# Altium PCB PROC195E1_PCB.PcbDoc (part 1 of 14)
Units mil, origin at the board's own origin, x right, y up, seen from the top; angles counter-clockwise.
Board outline 3110.24 x 2500 mil, 10 copper layers (Top Layer, L02_GND1, L03_SIG1, L04_GND2, L05_PWR1, L06_PWR2, L07_GND3, L08_SIG2, L09_GND4, Bottom Layer), stack 66.407 mil thick; 571 components, 538 nets, 6726 pads, 1286 vias.
Unrouted connection lines stored in the file: 4.
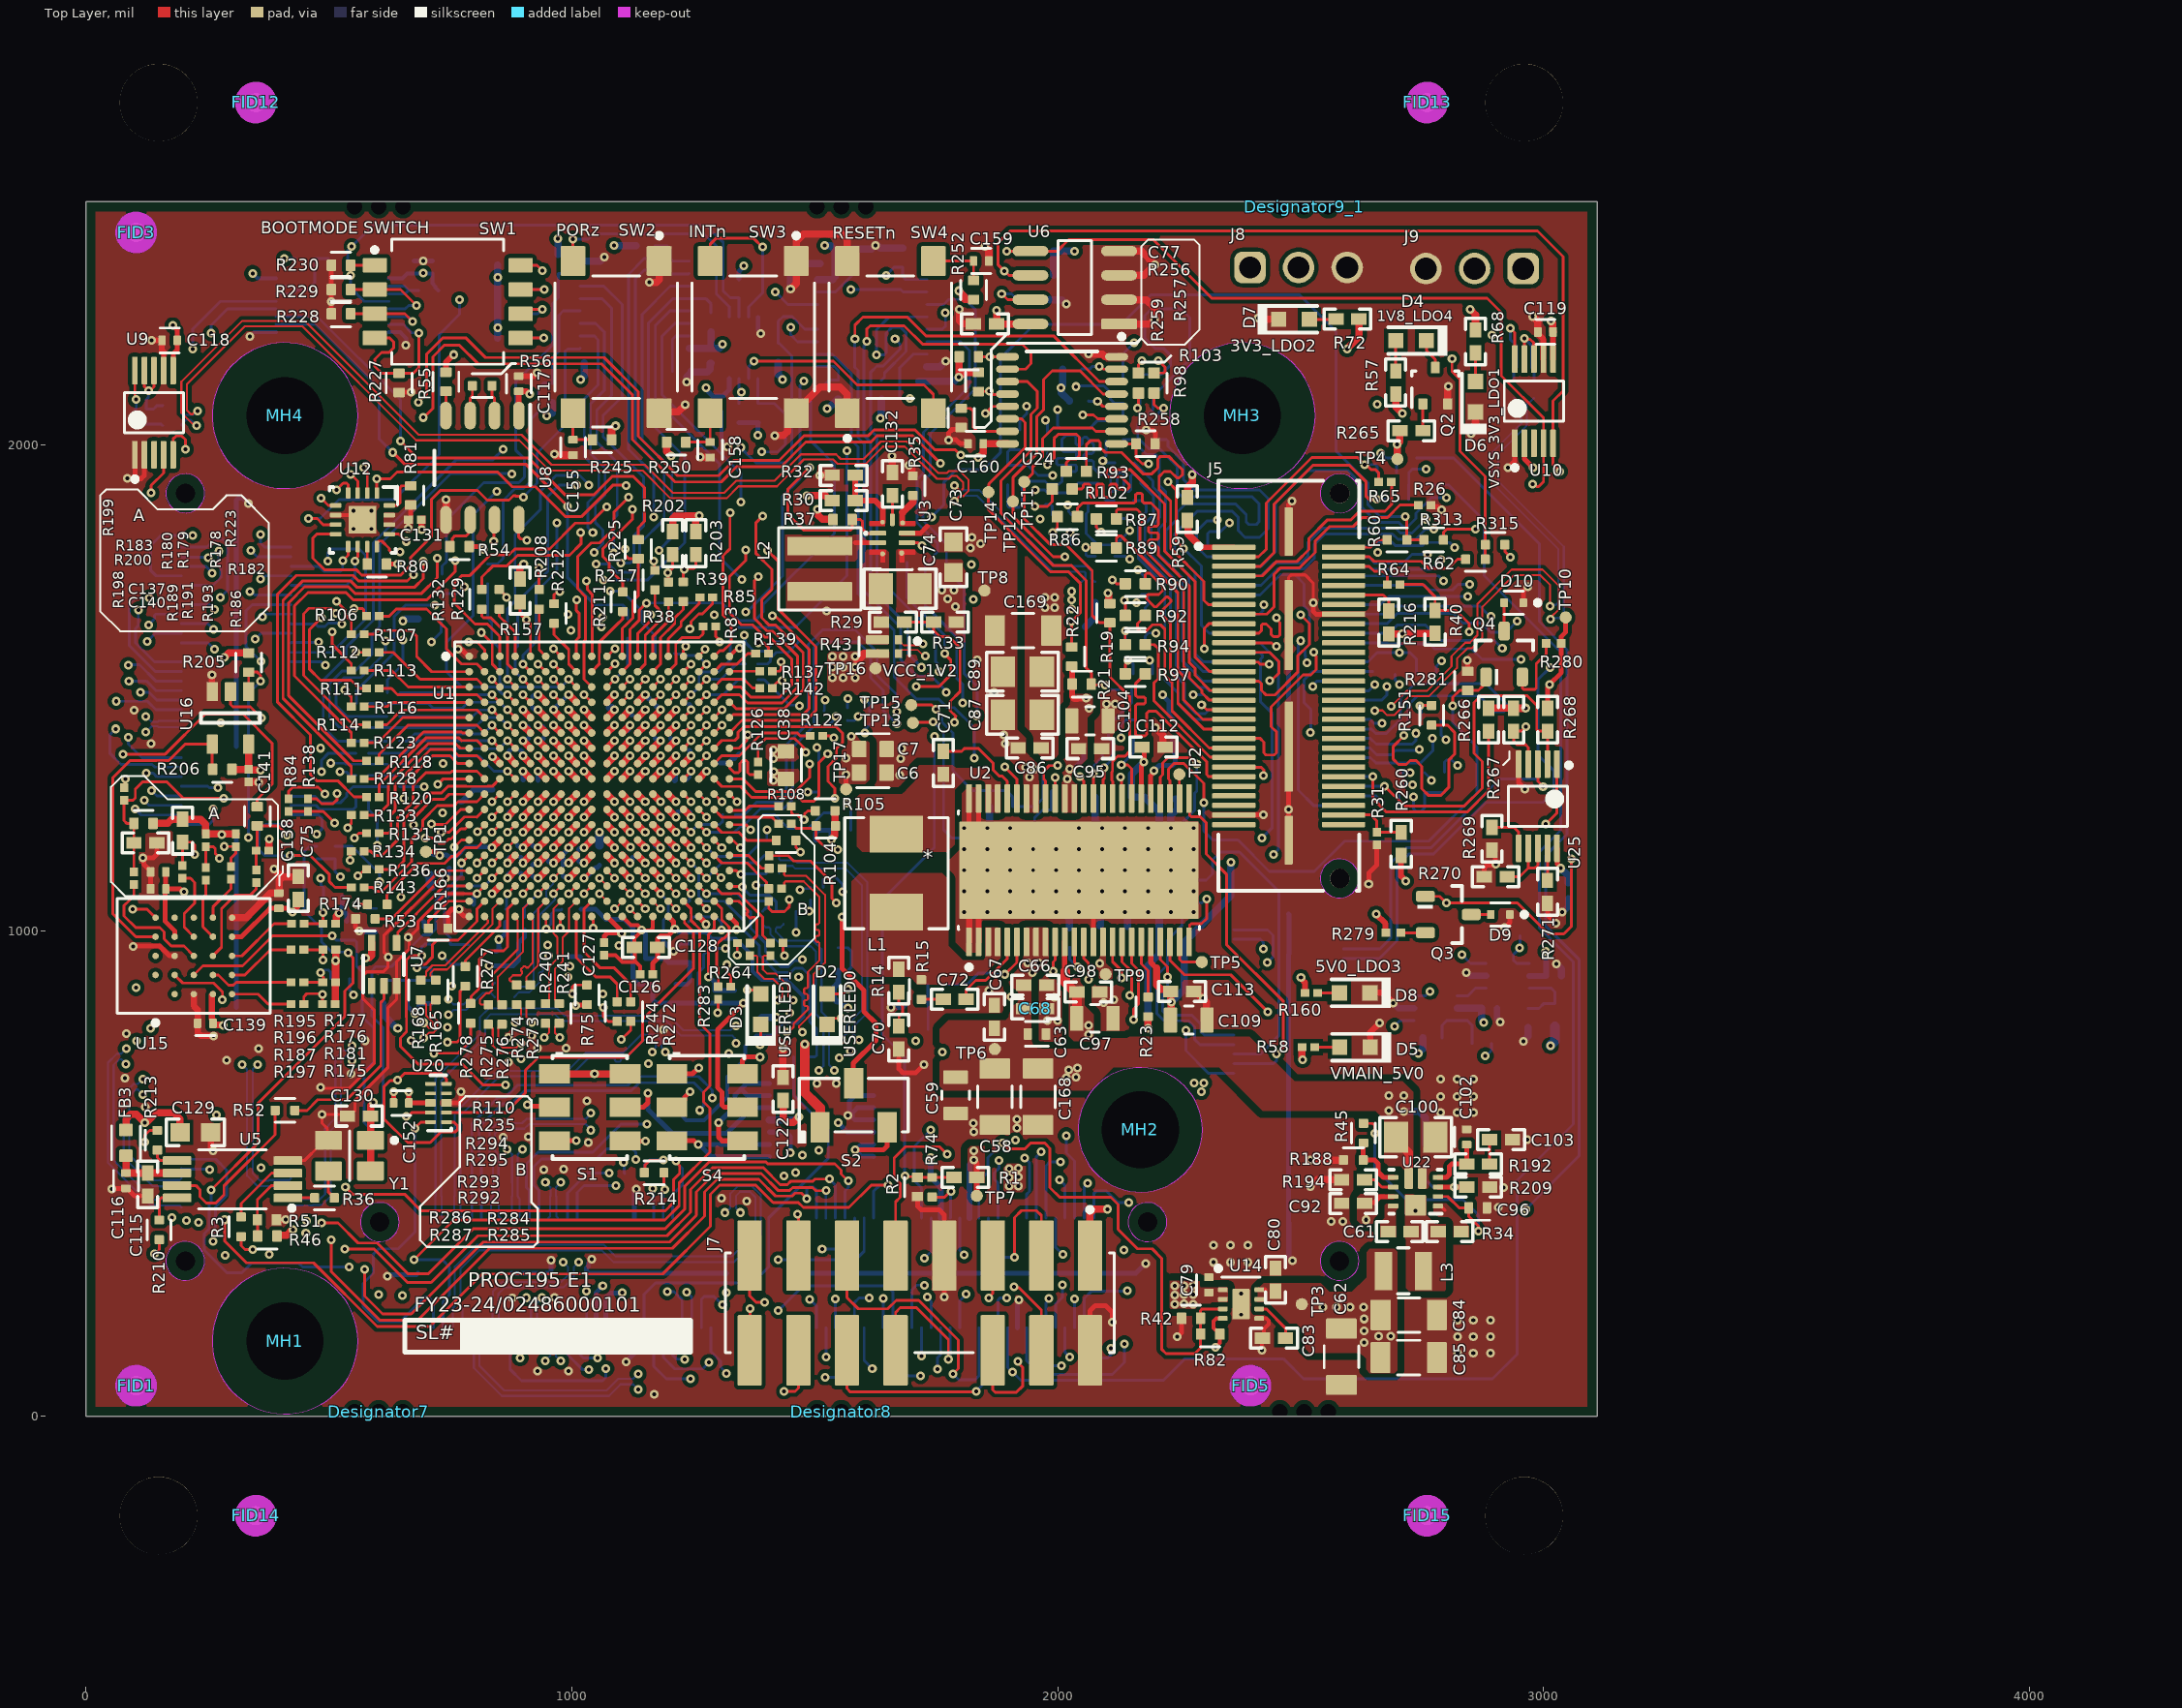
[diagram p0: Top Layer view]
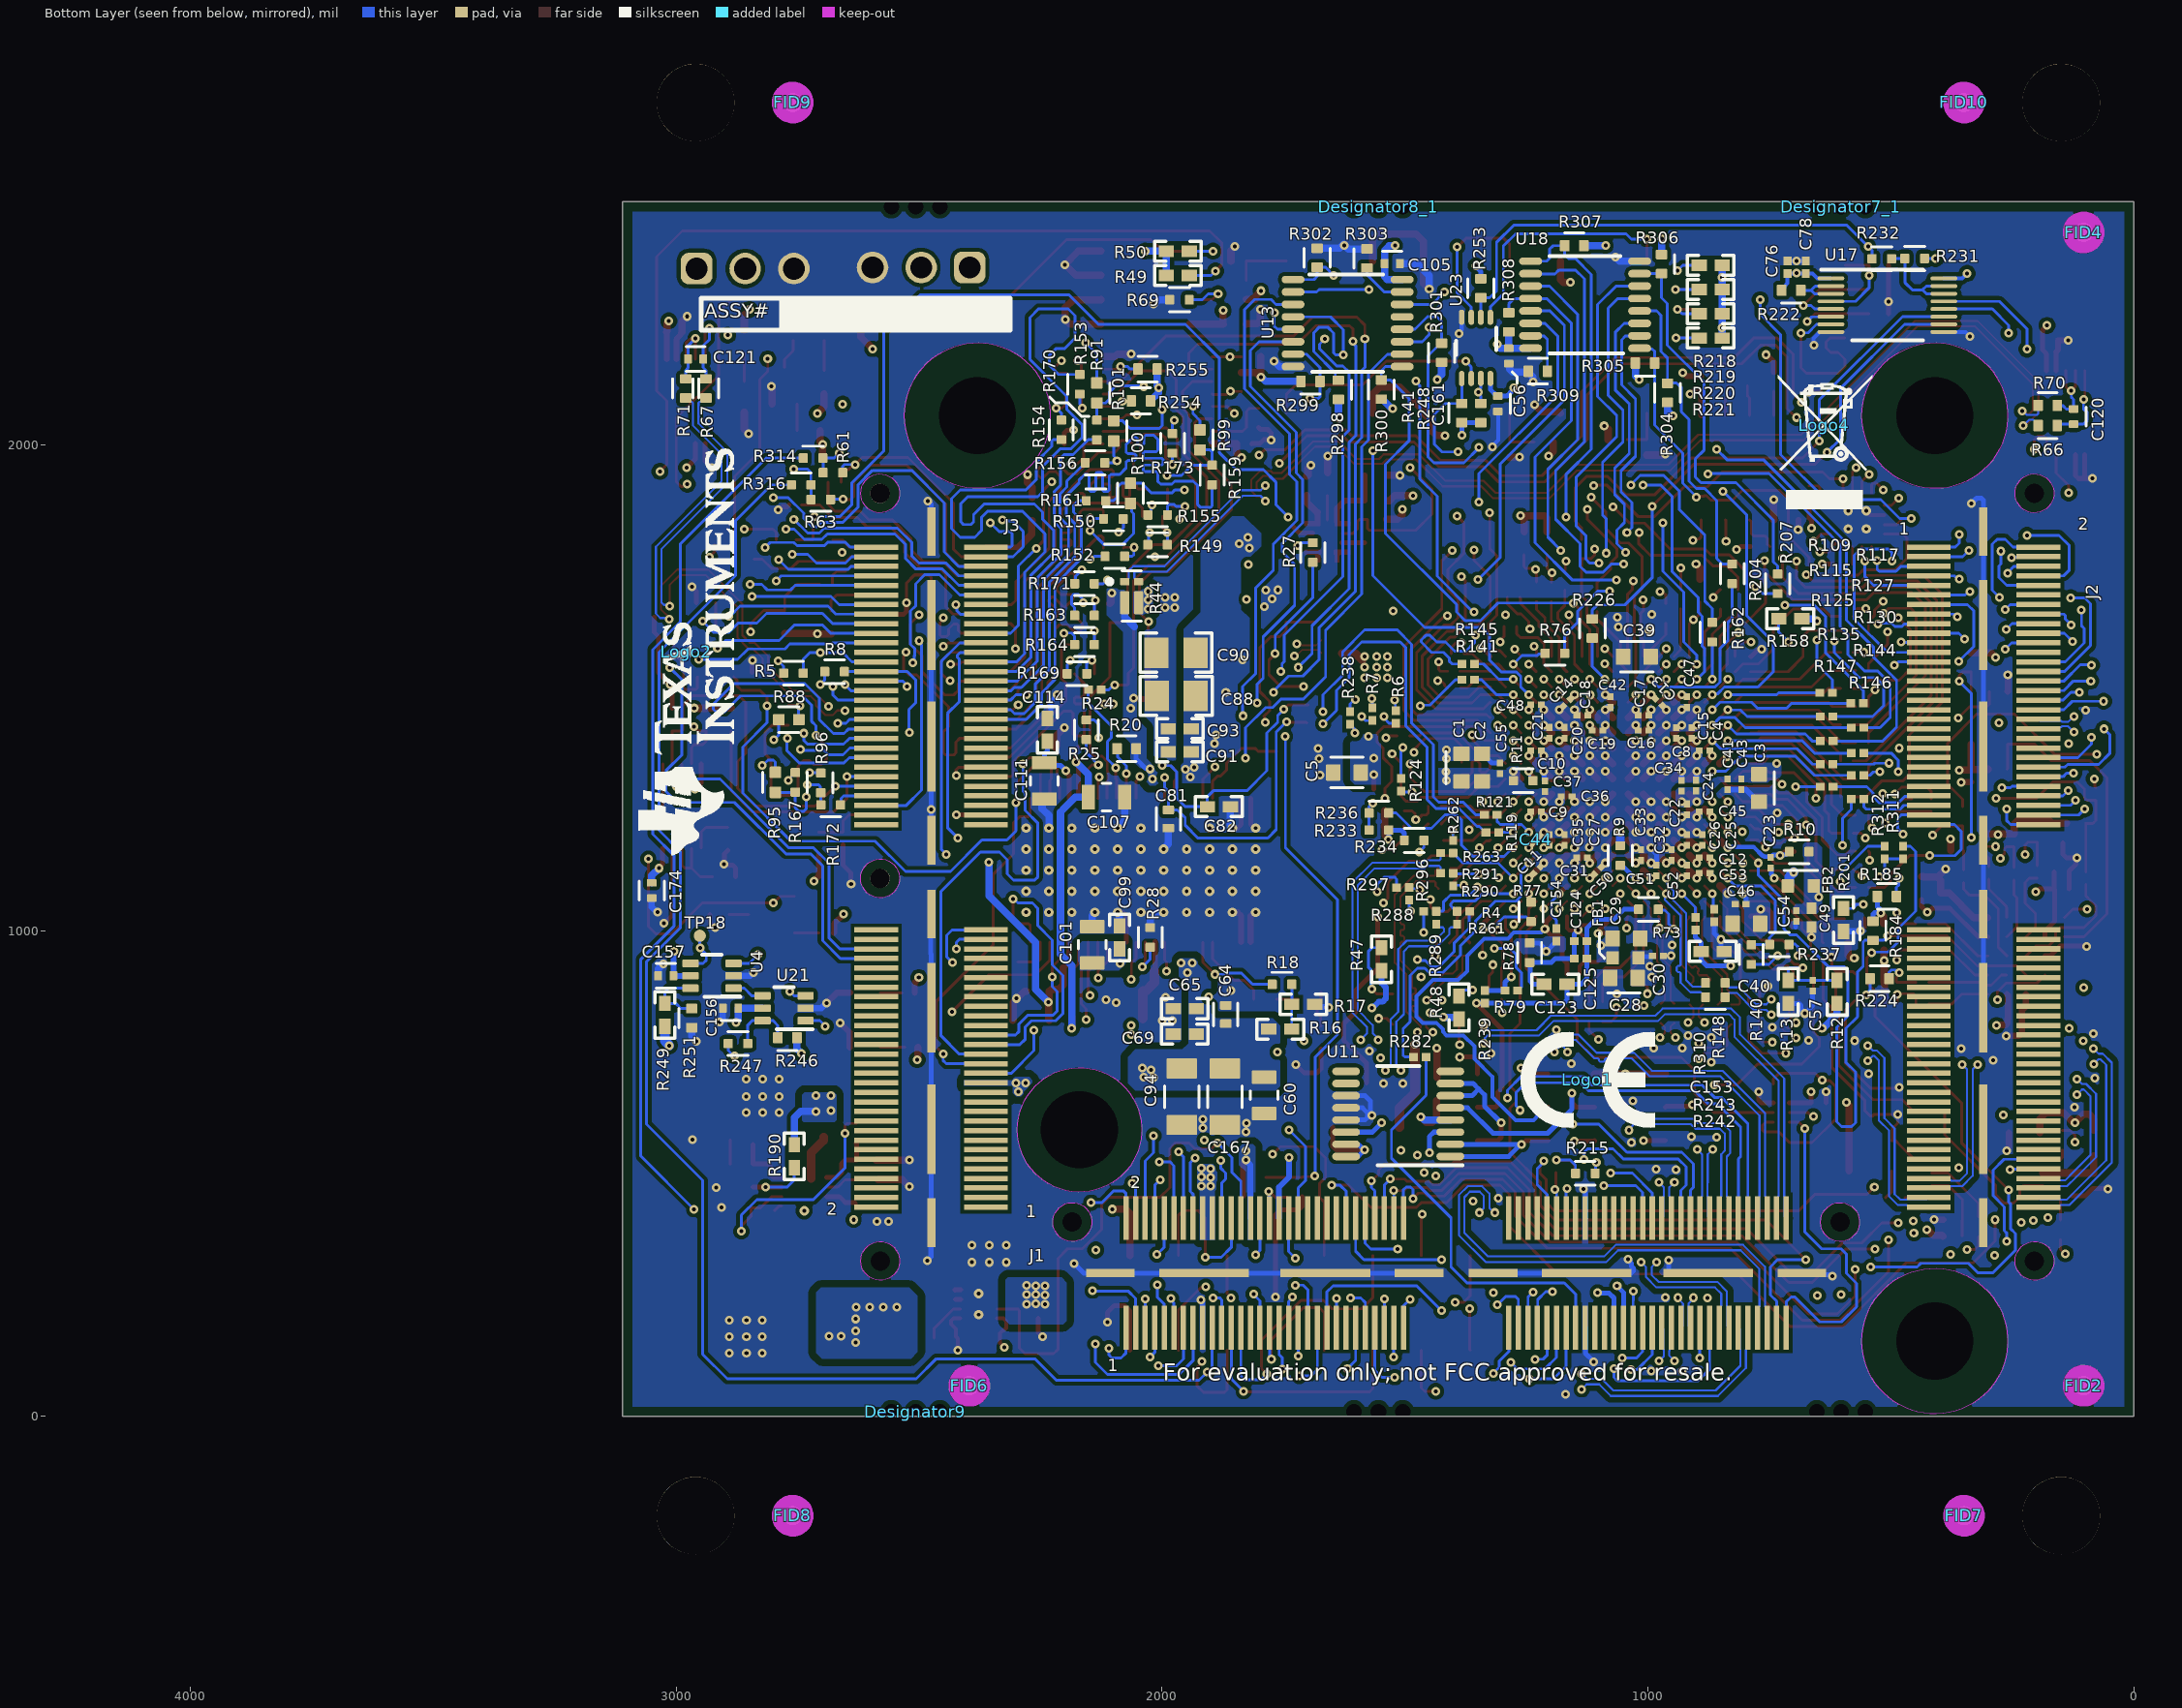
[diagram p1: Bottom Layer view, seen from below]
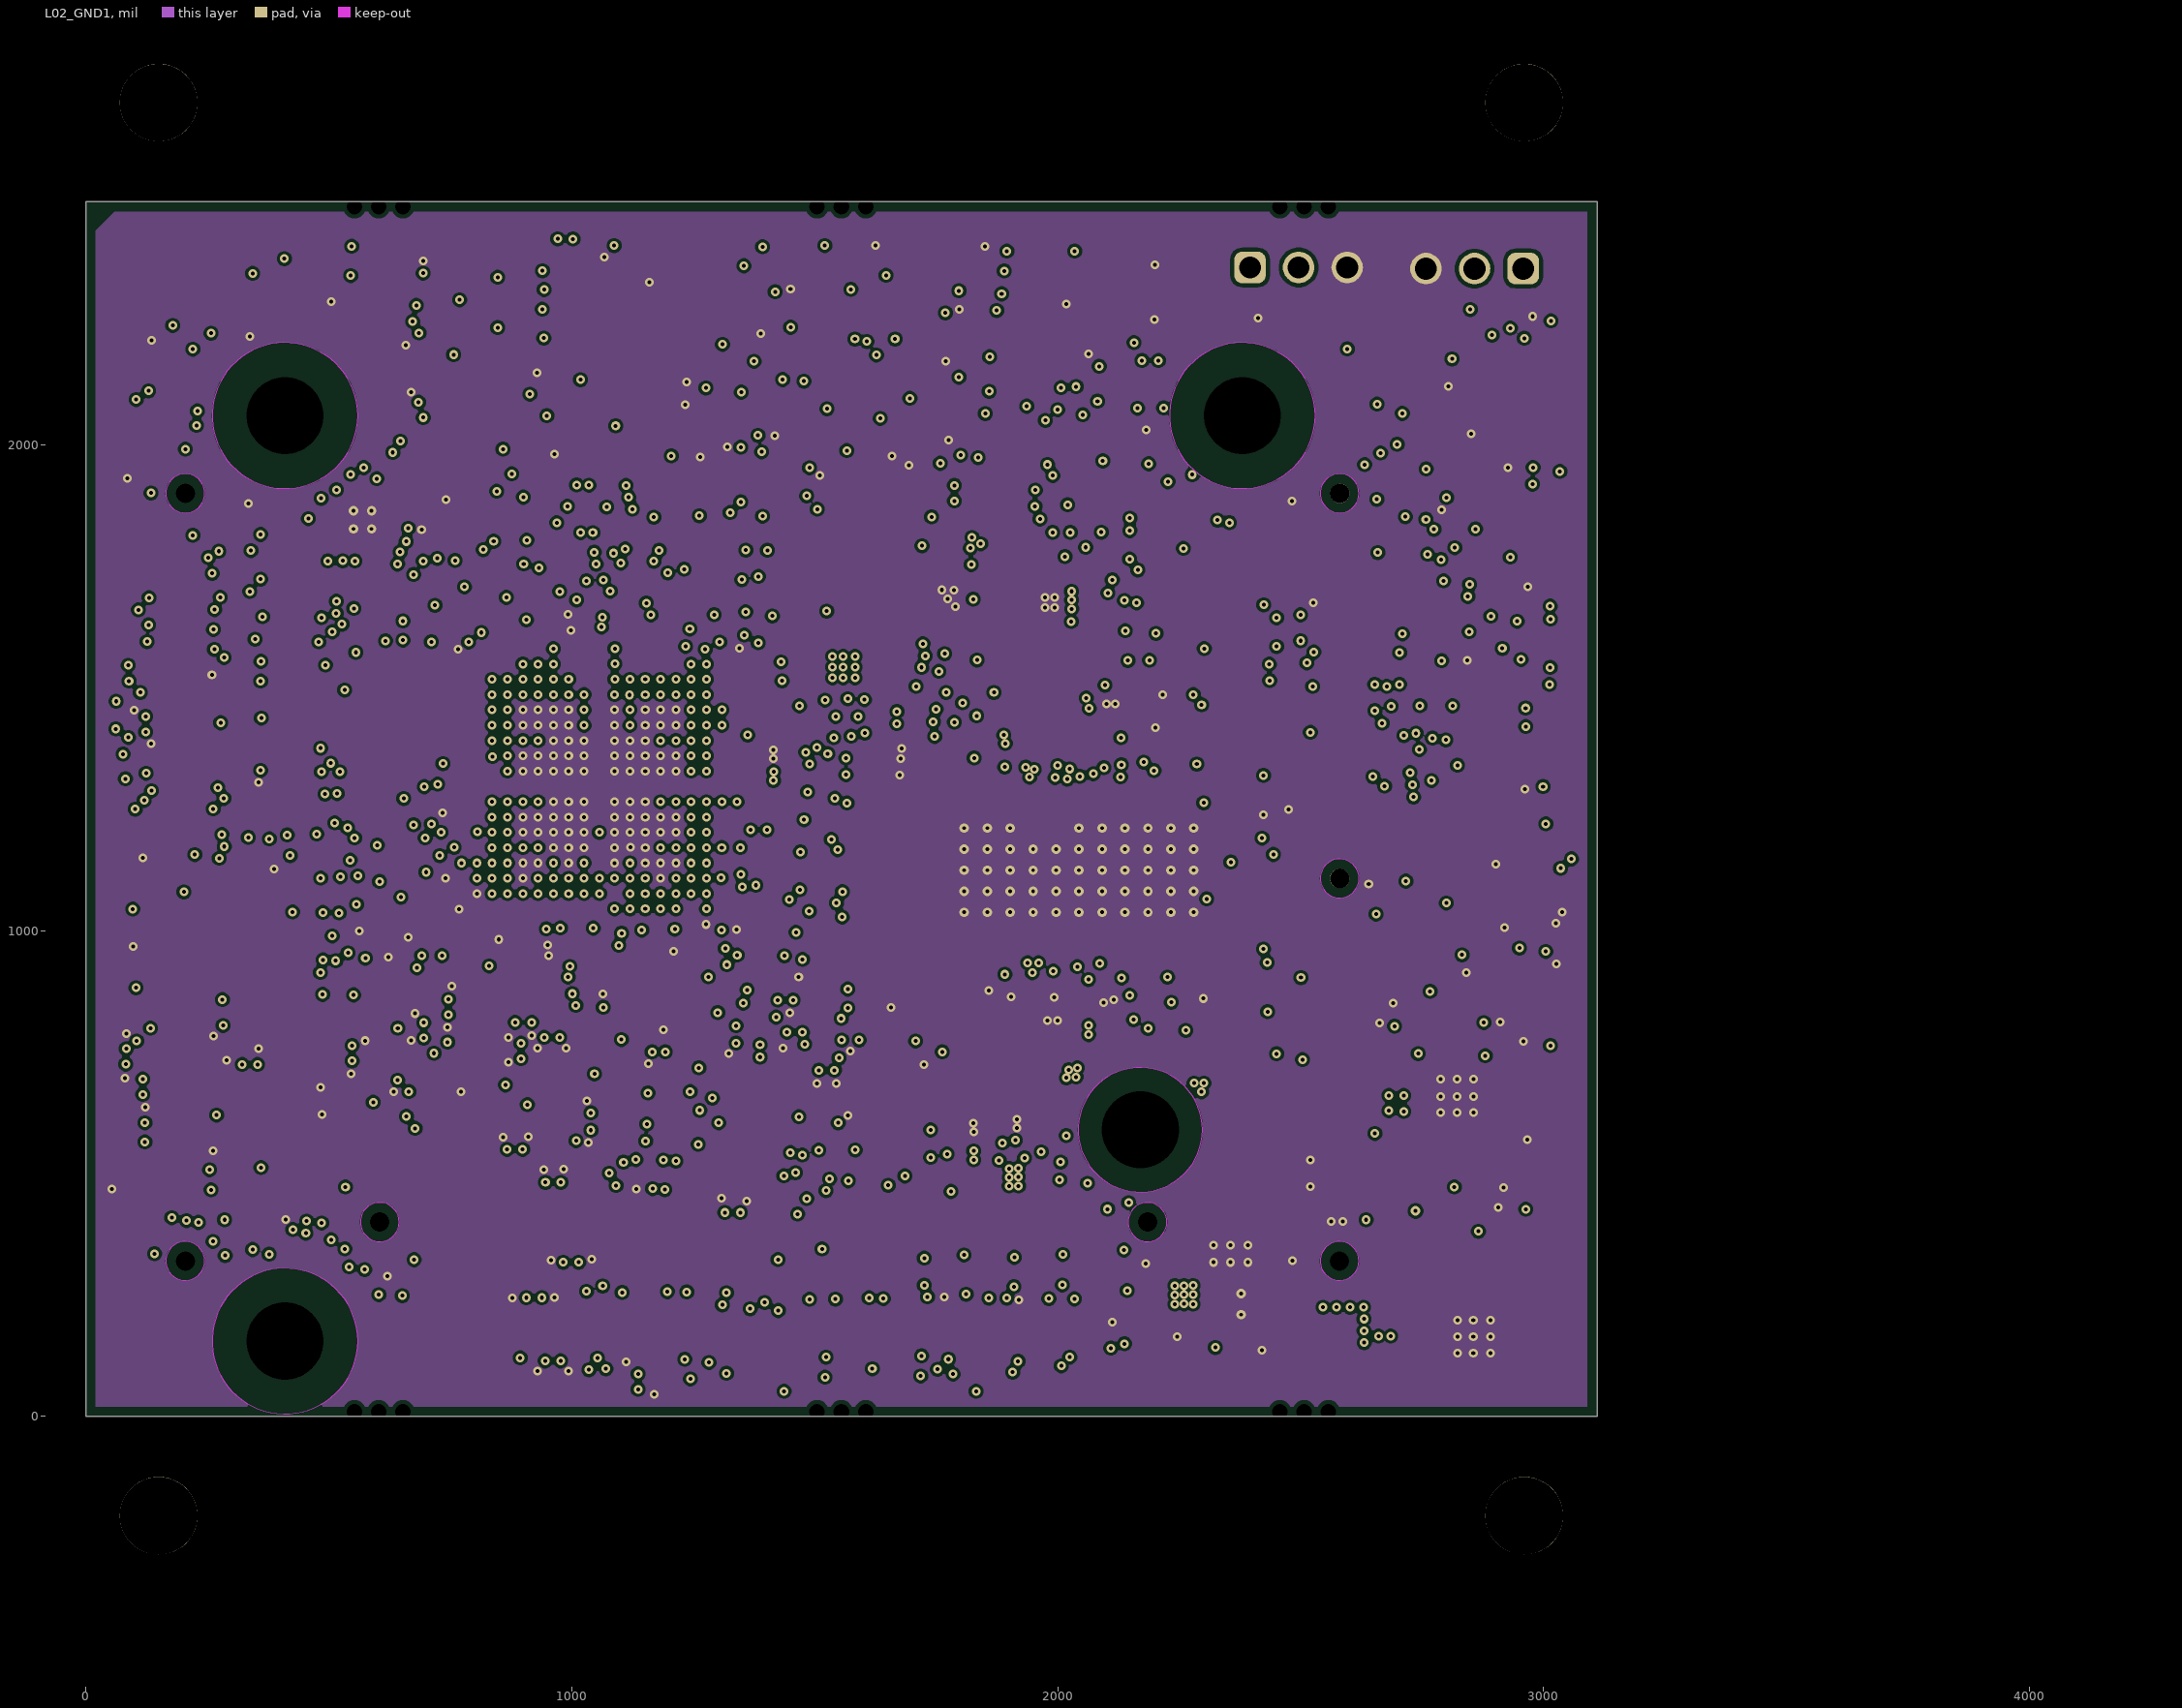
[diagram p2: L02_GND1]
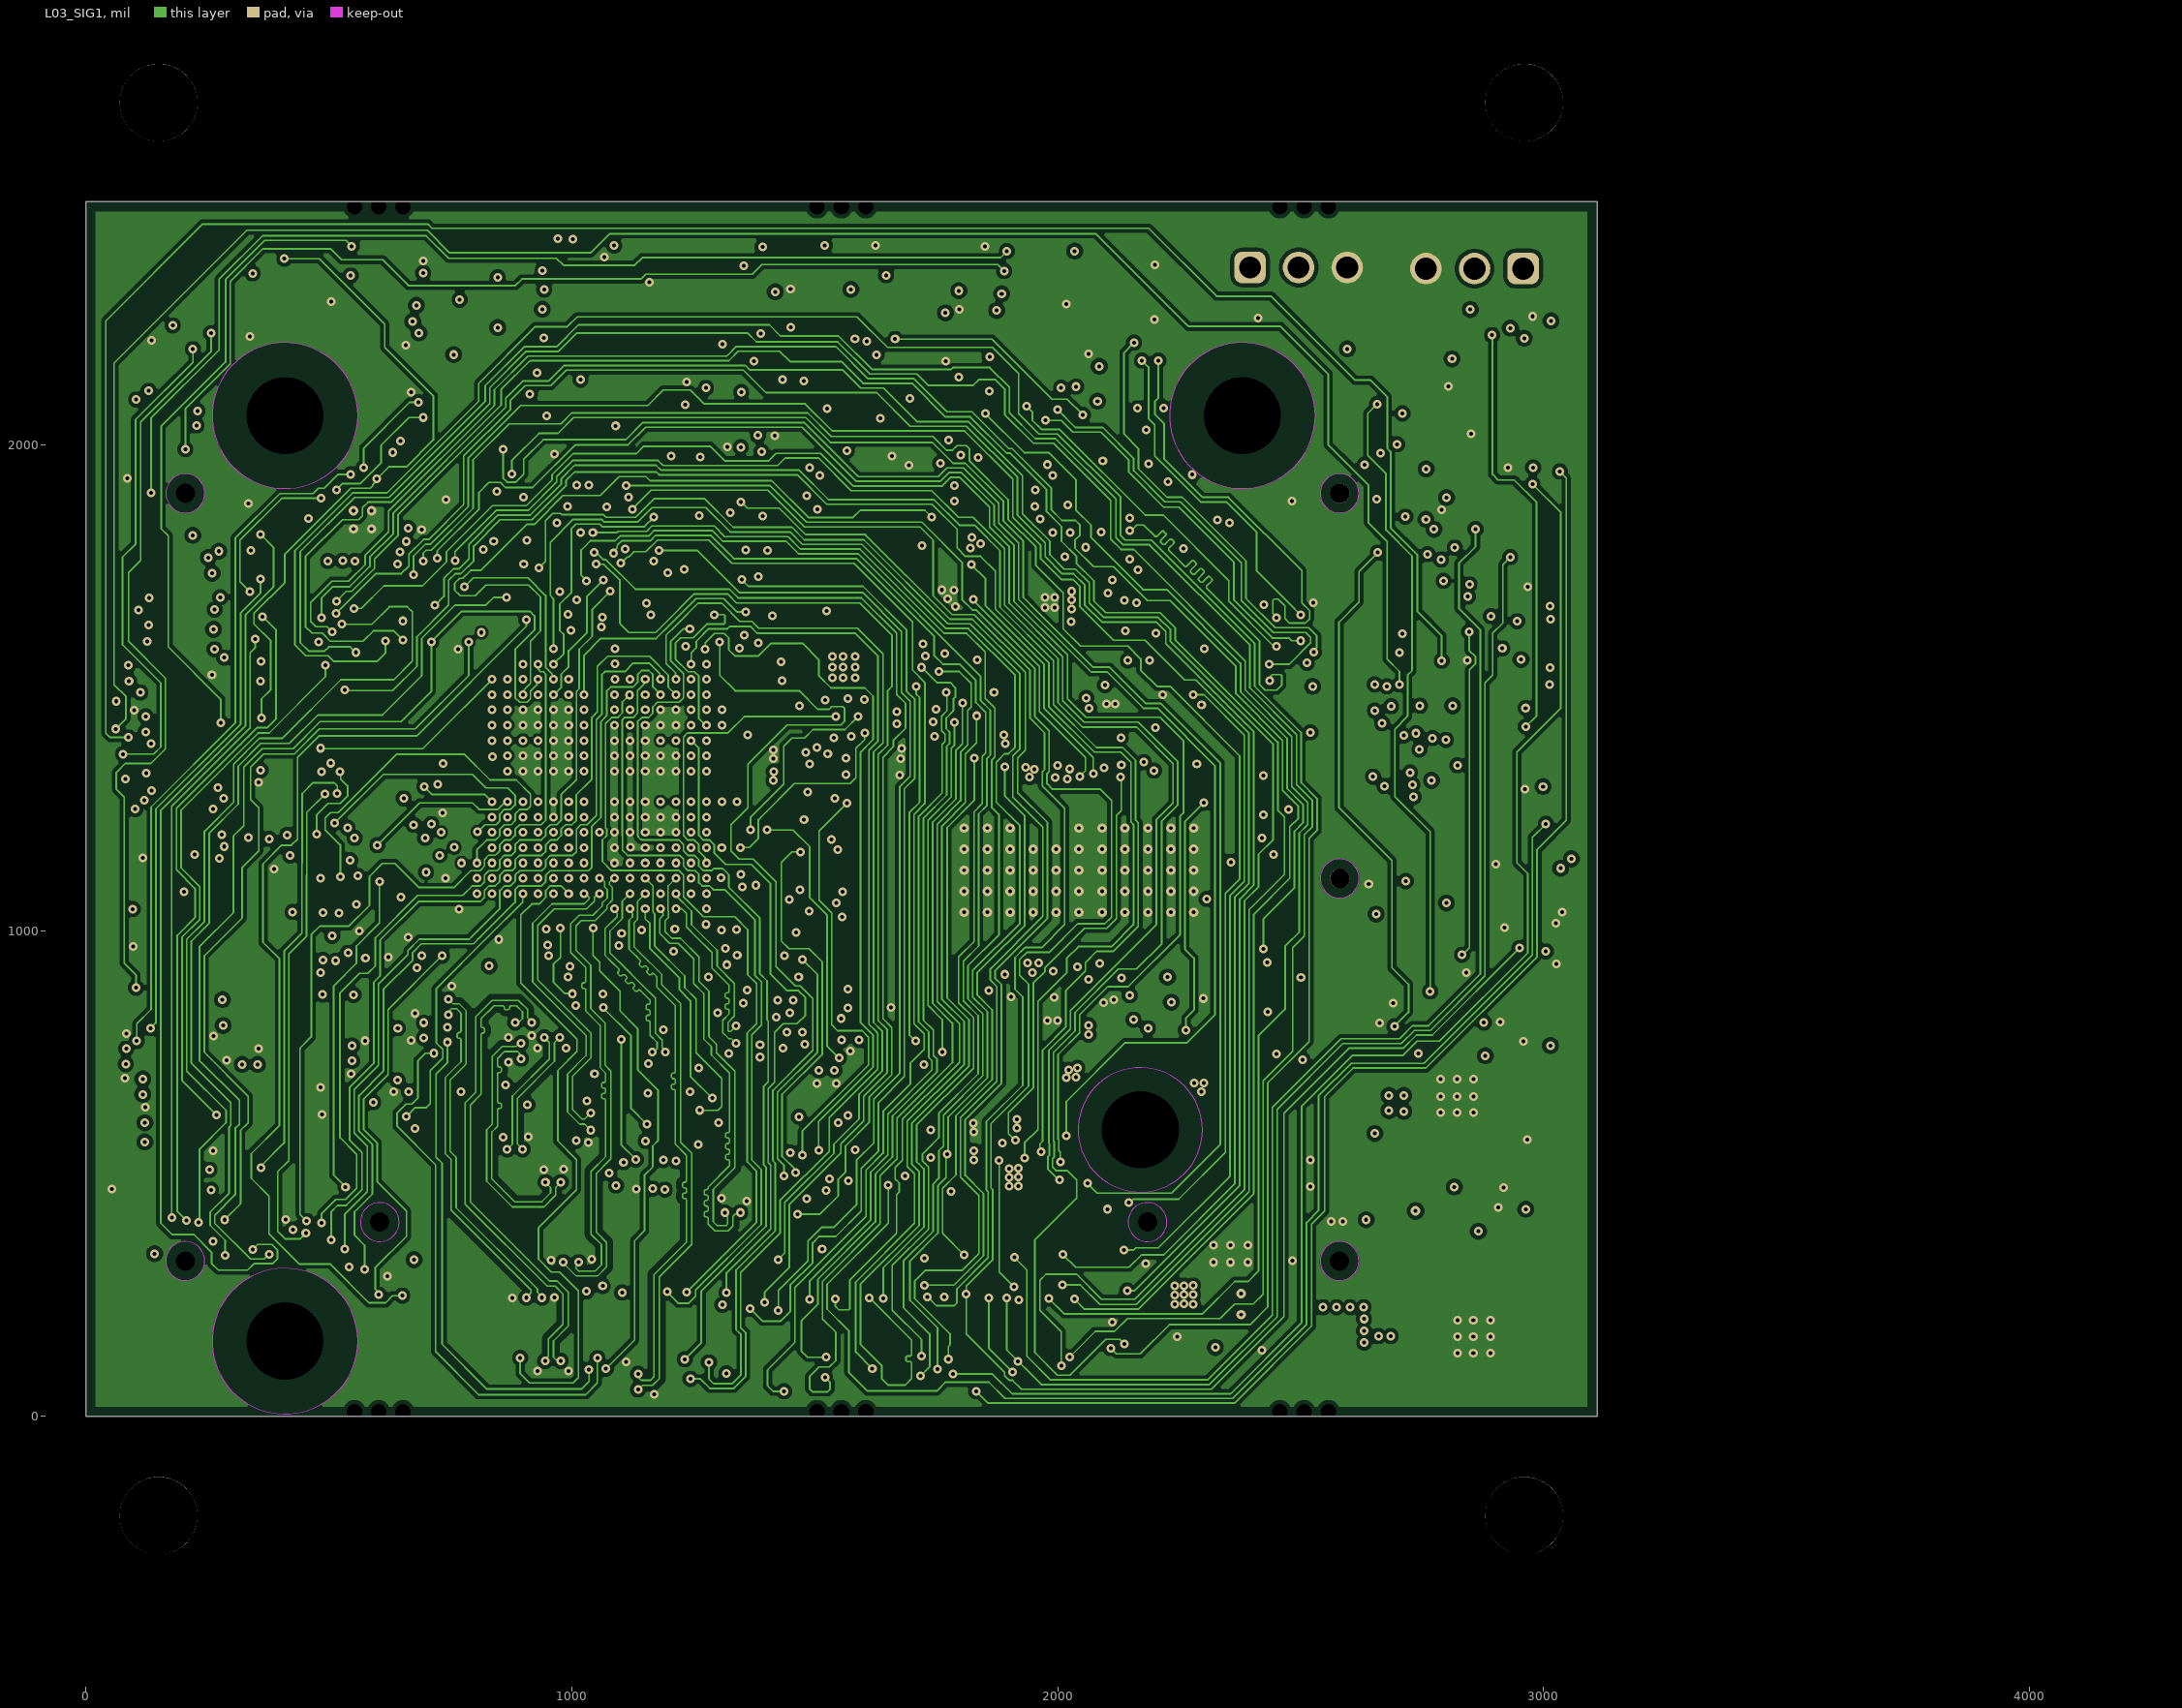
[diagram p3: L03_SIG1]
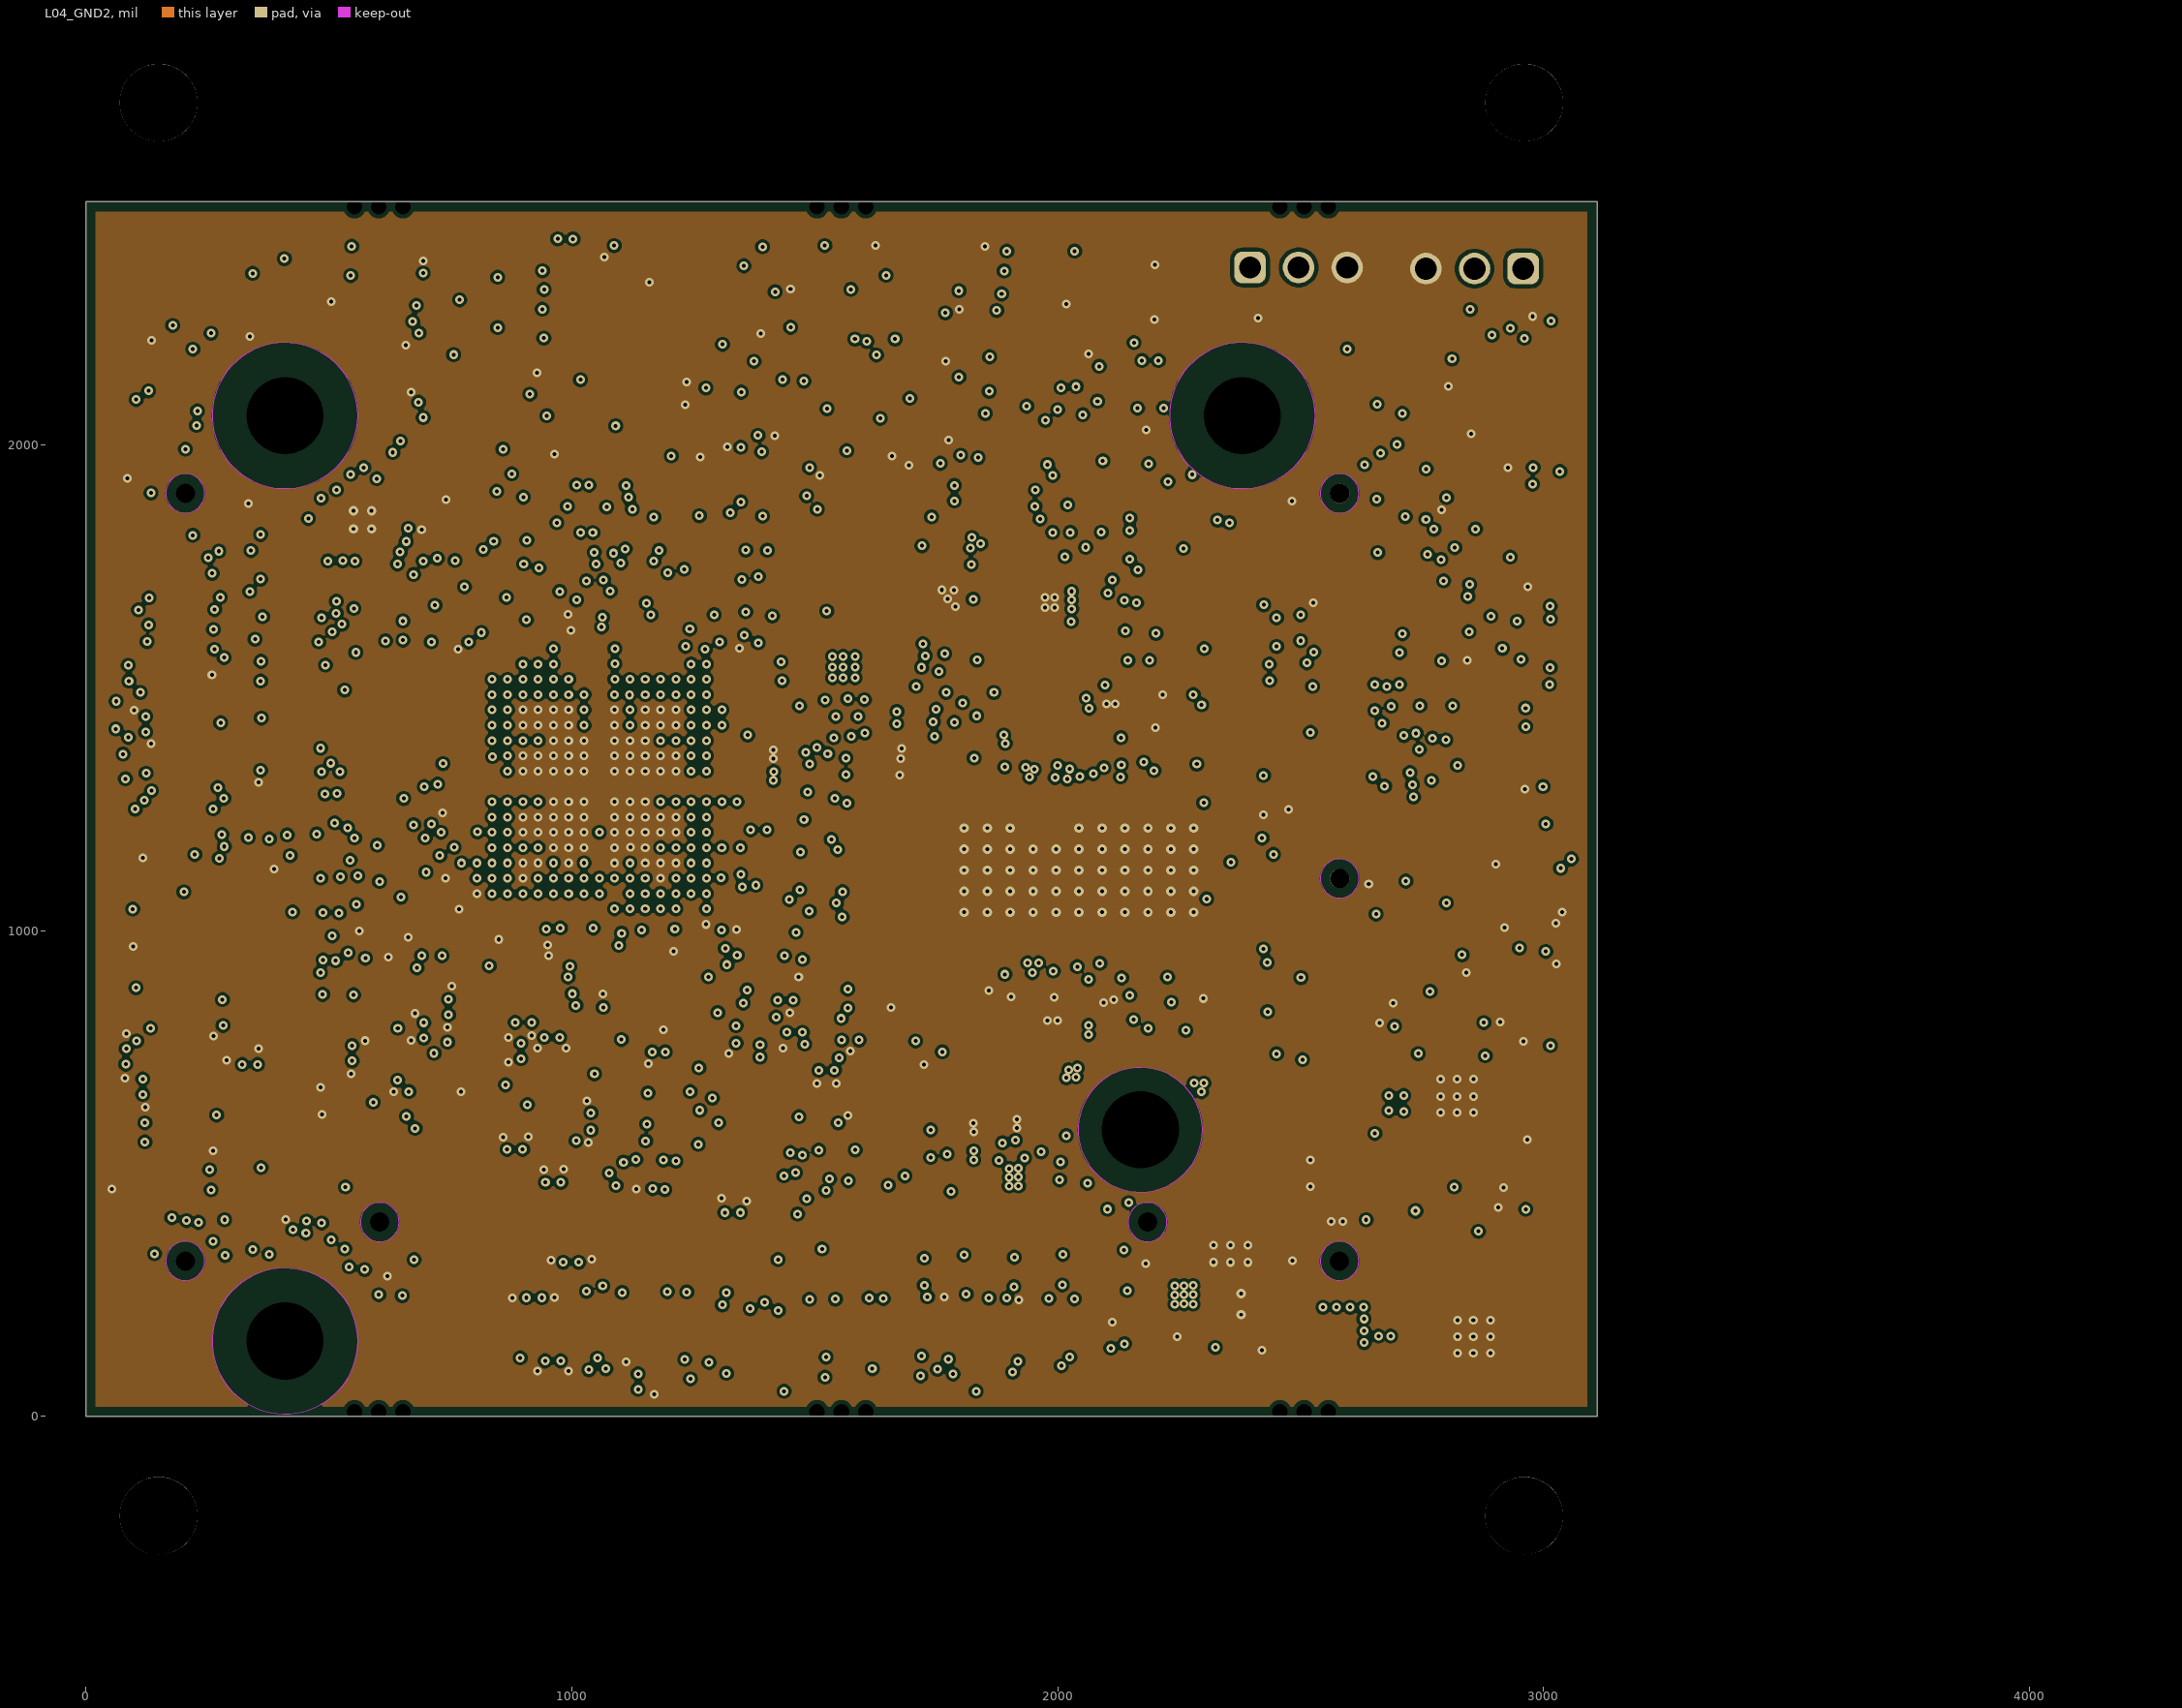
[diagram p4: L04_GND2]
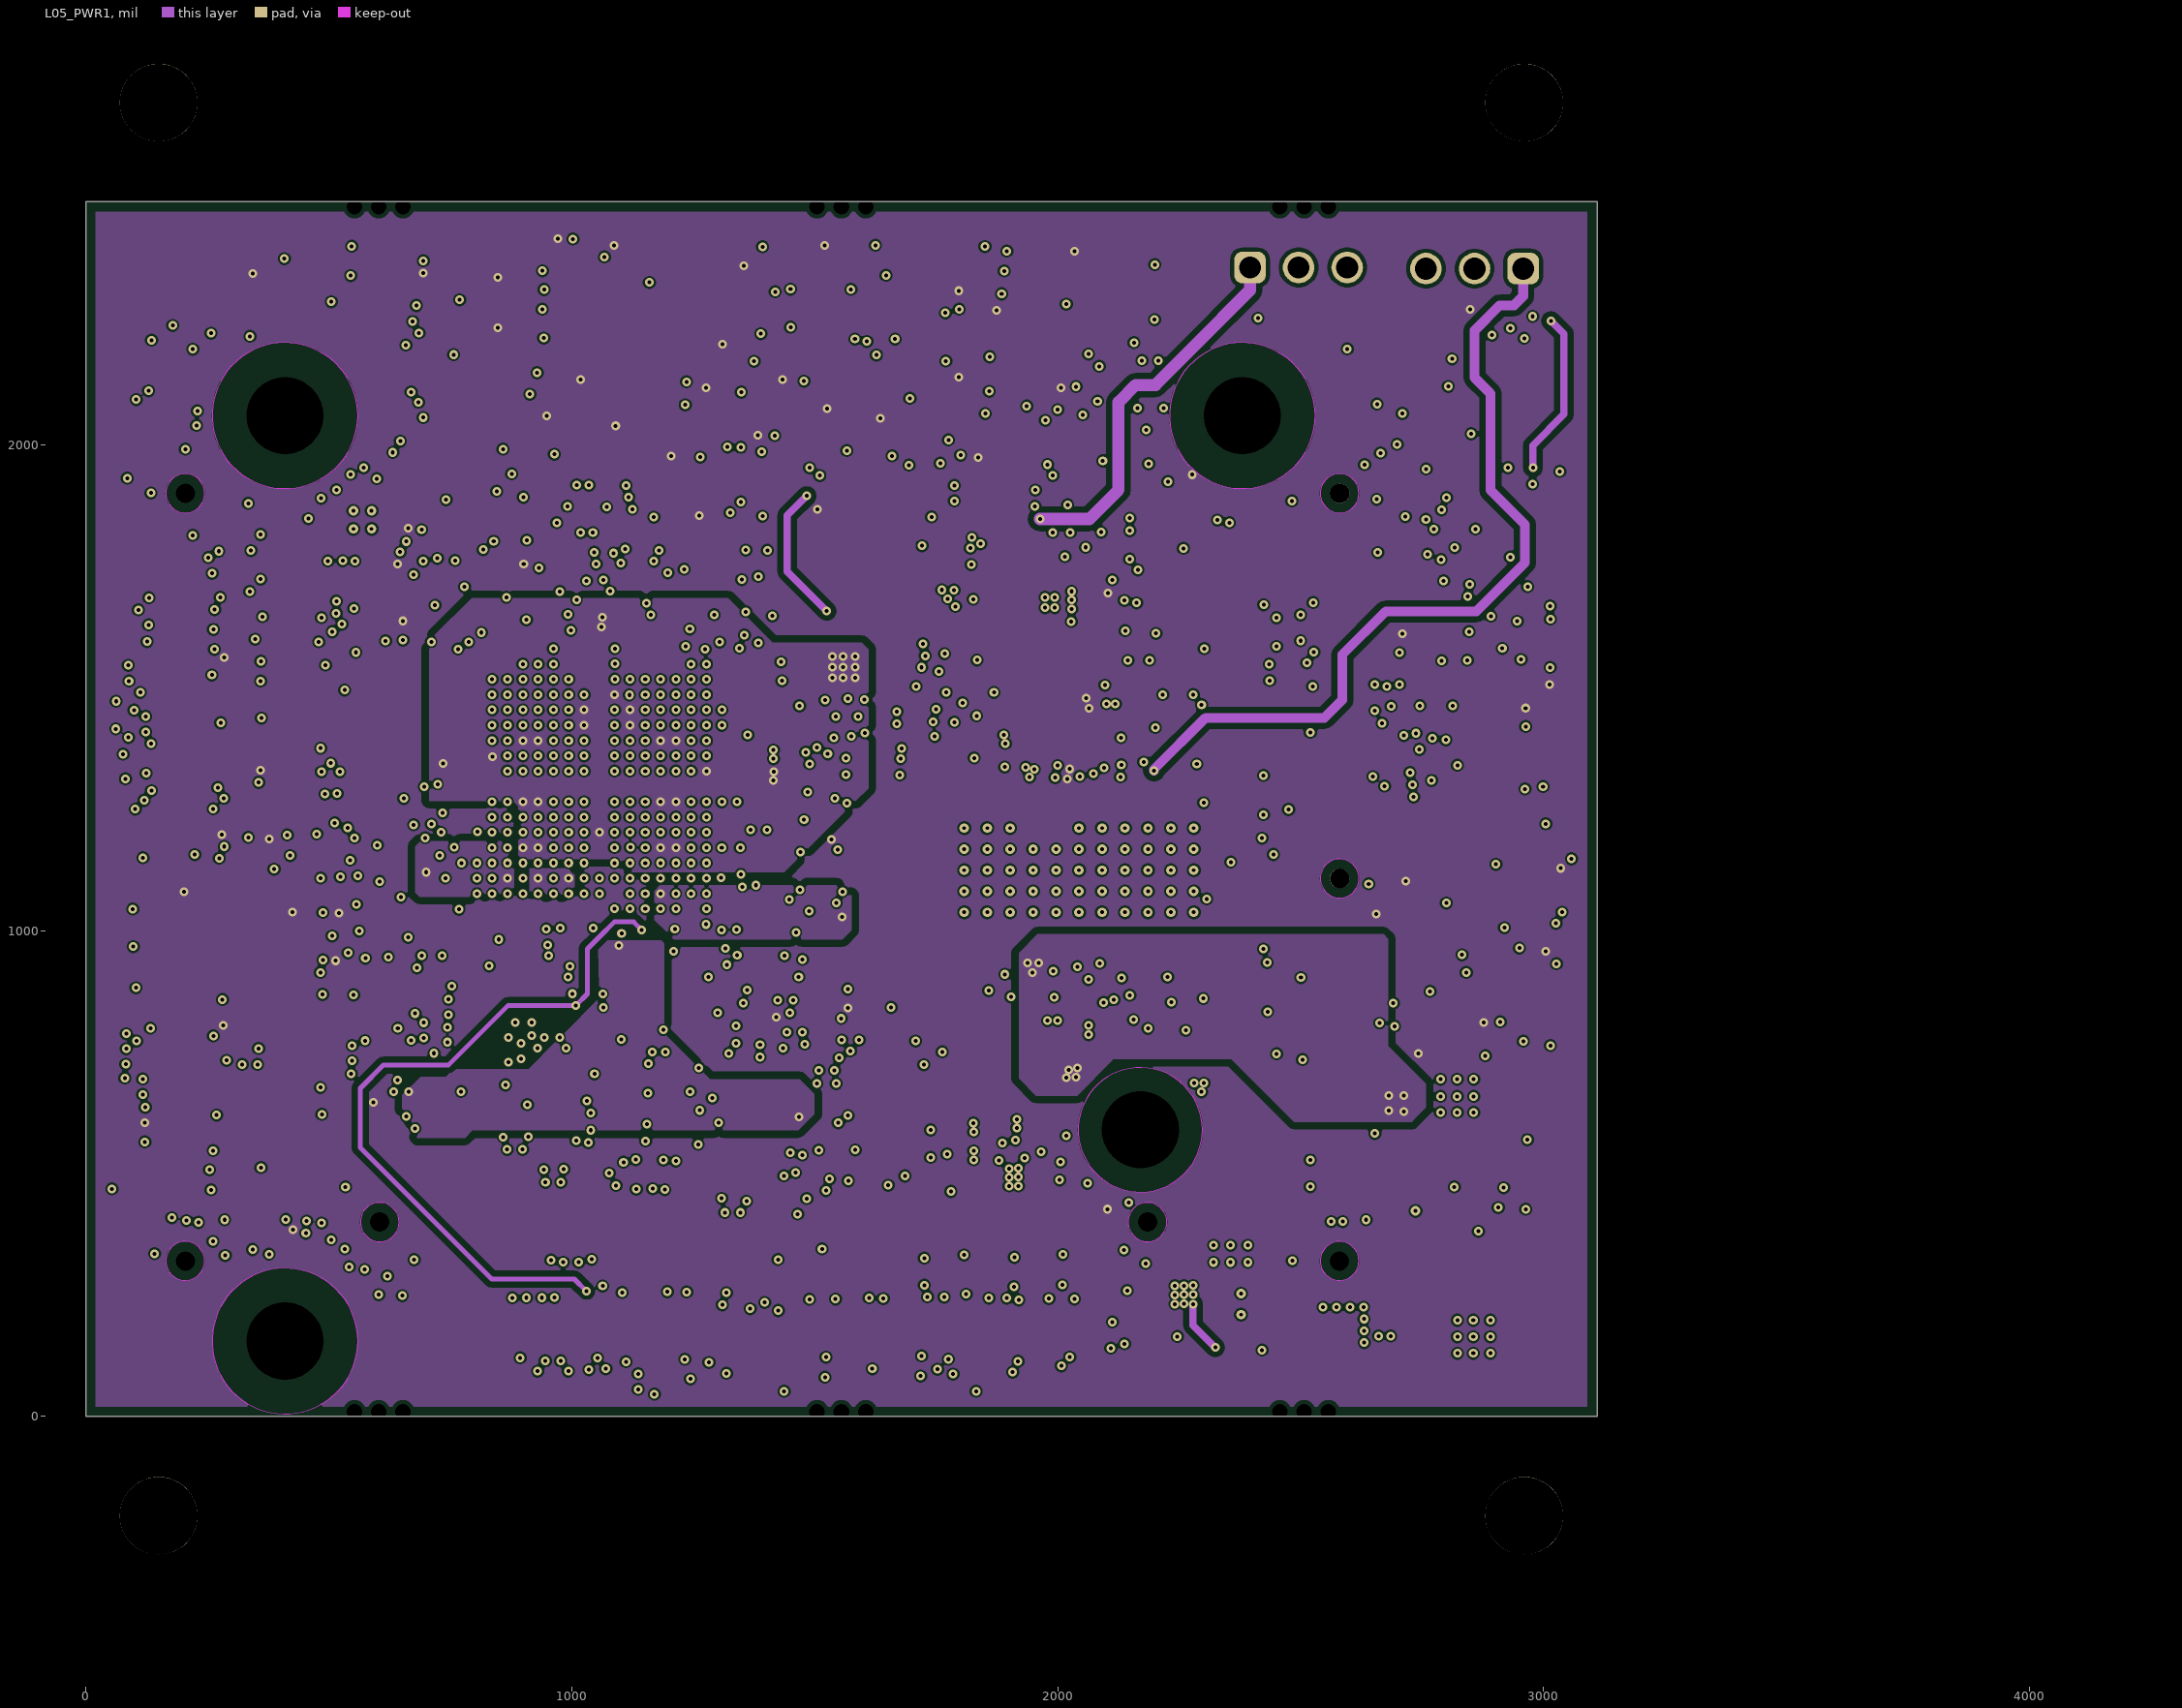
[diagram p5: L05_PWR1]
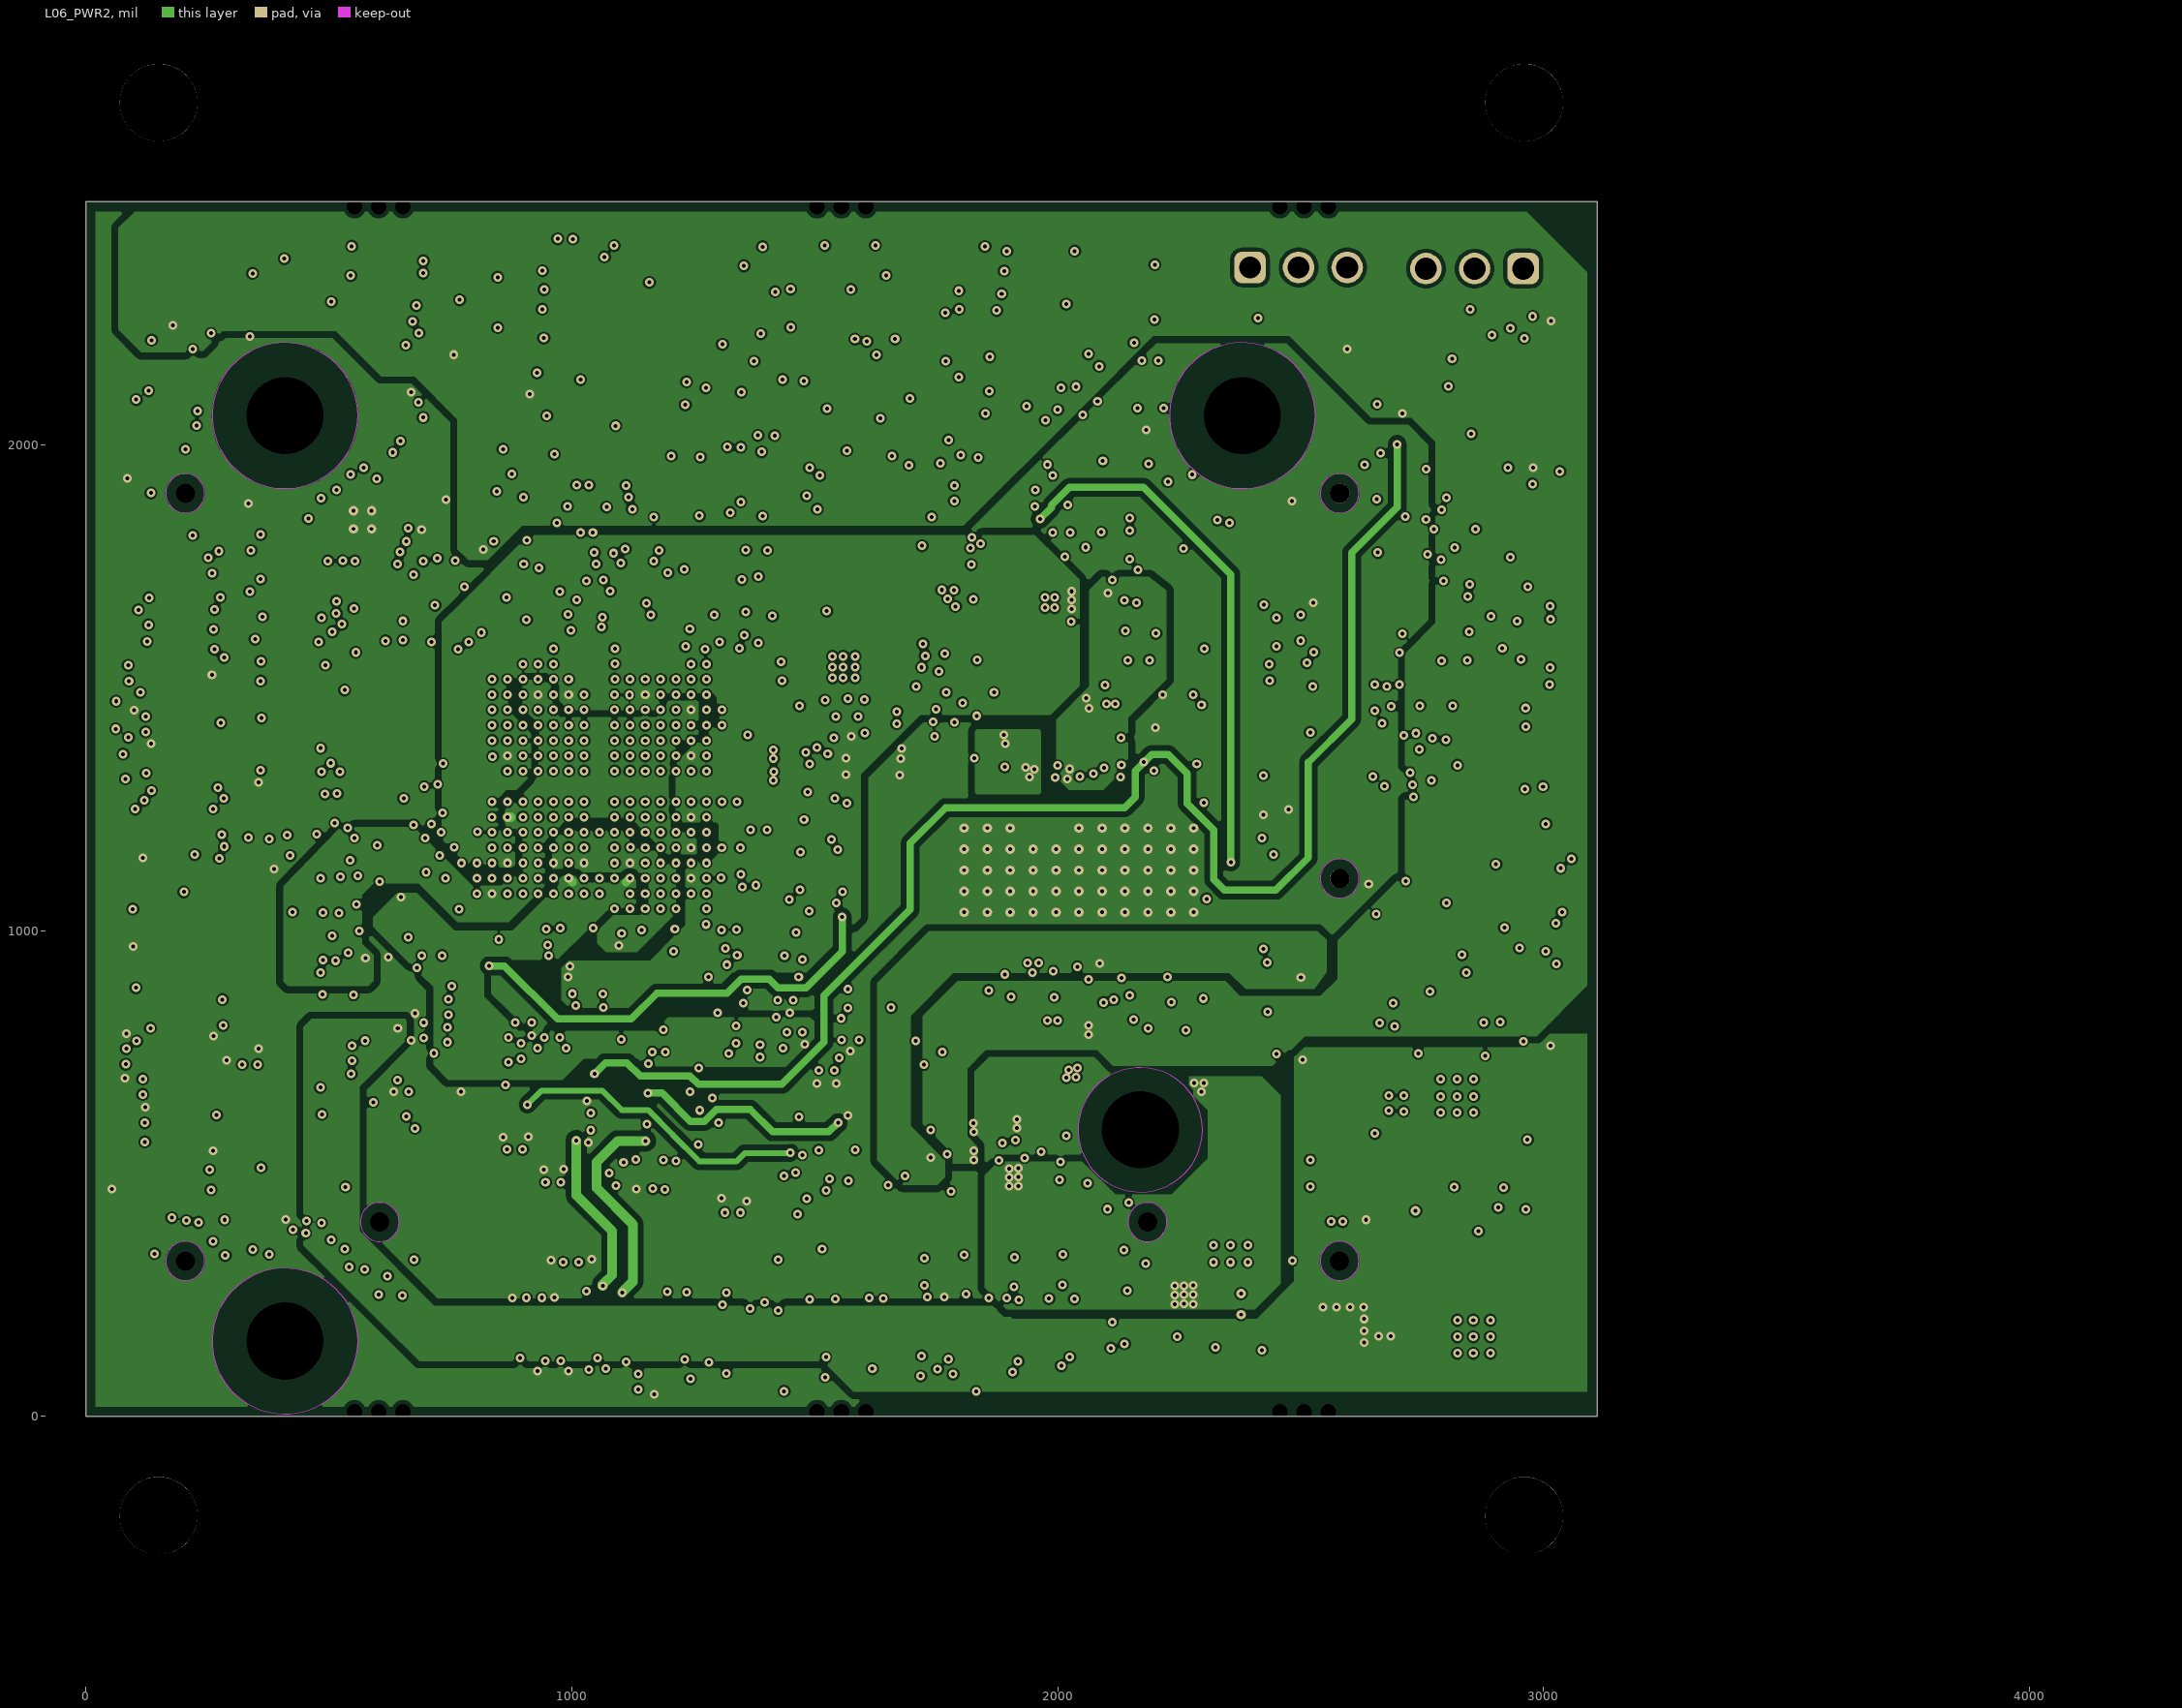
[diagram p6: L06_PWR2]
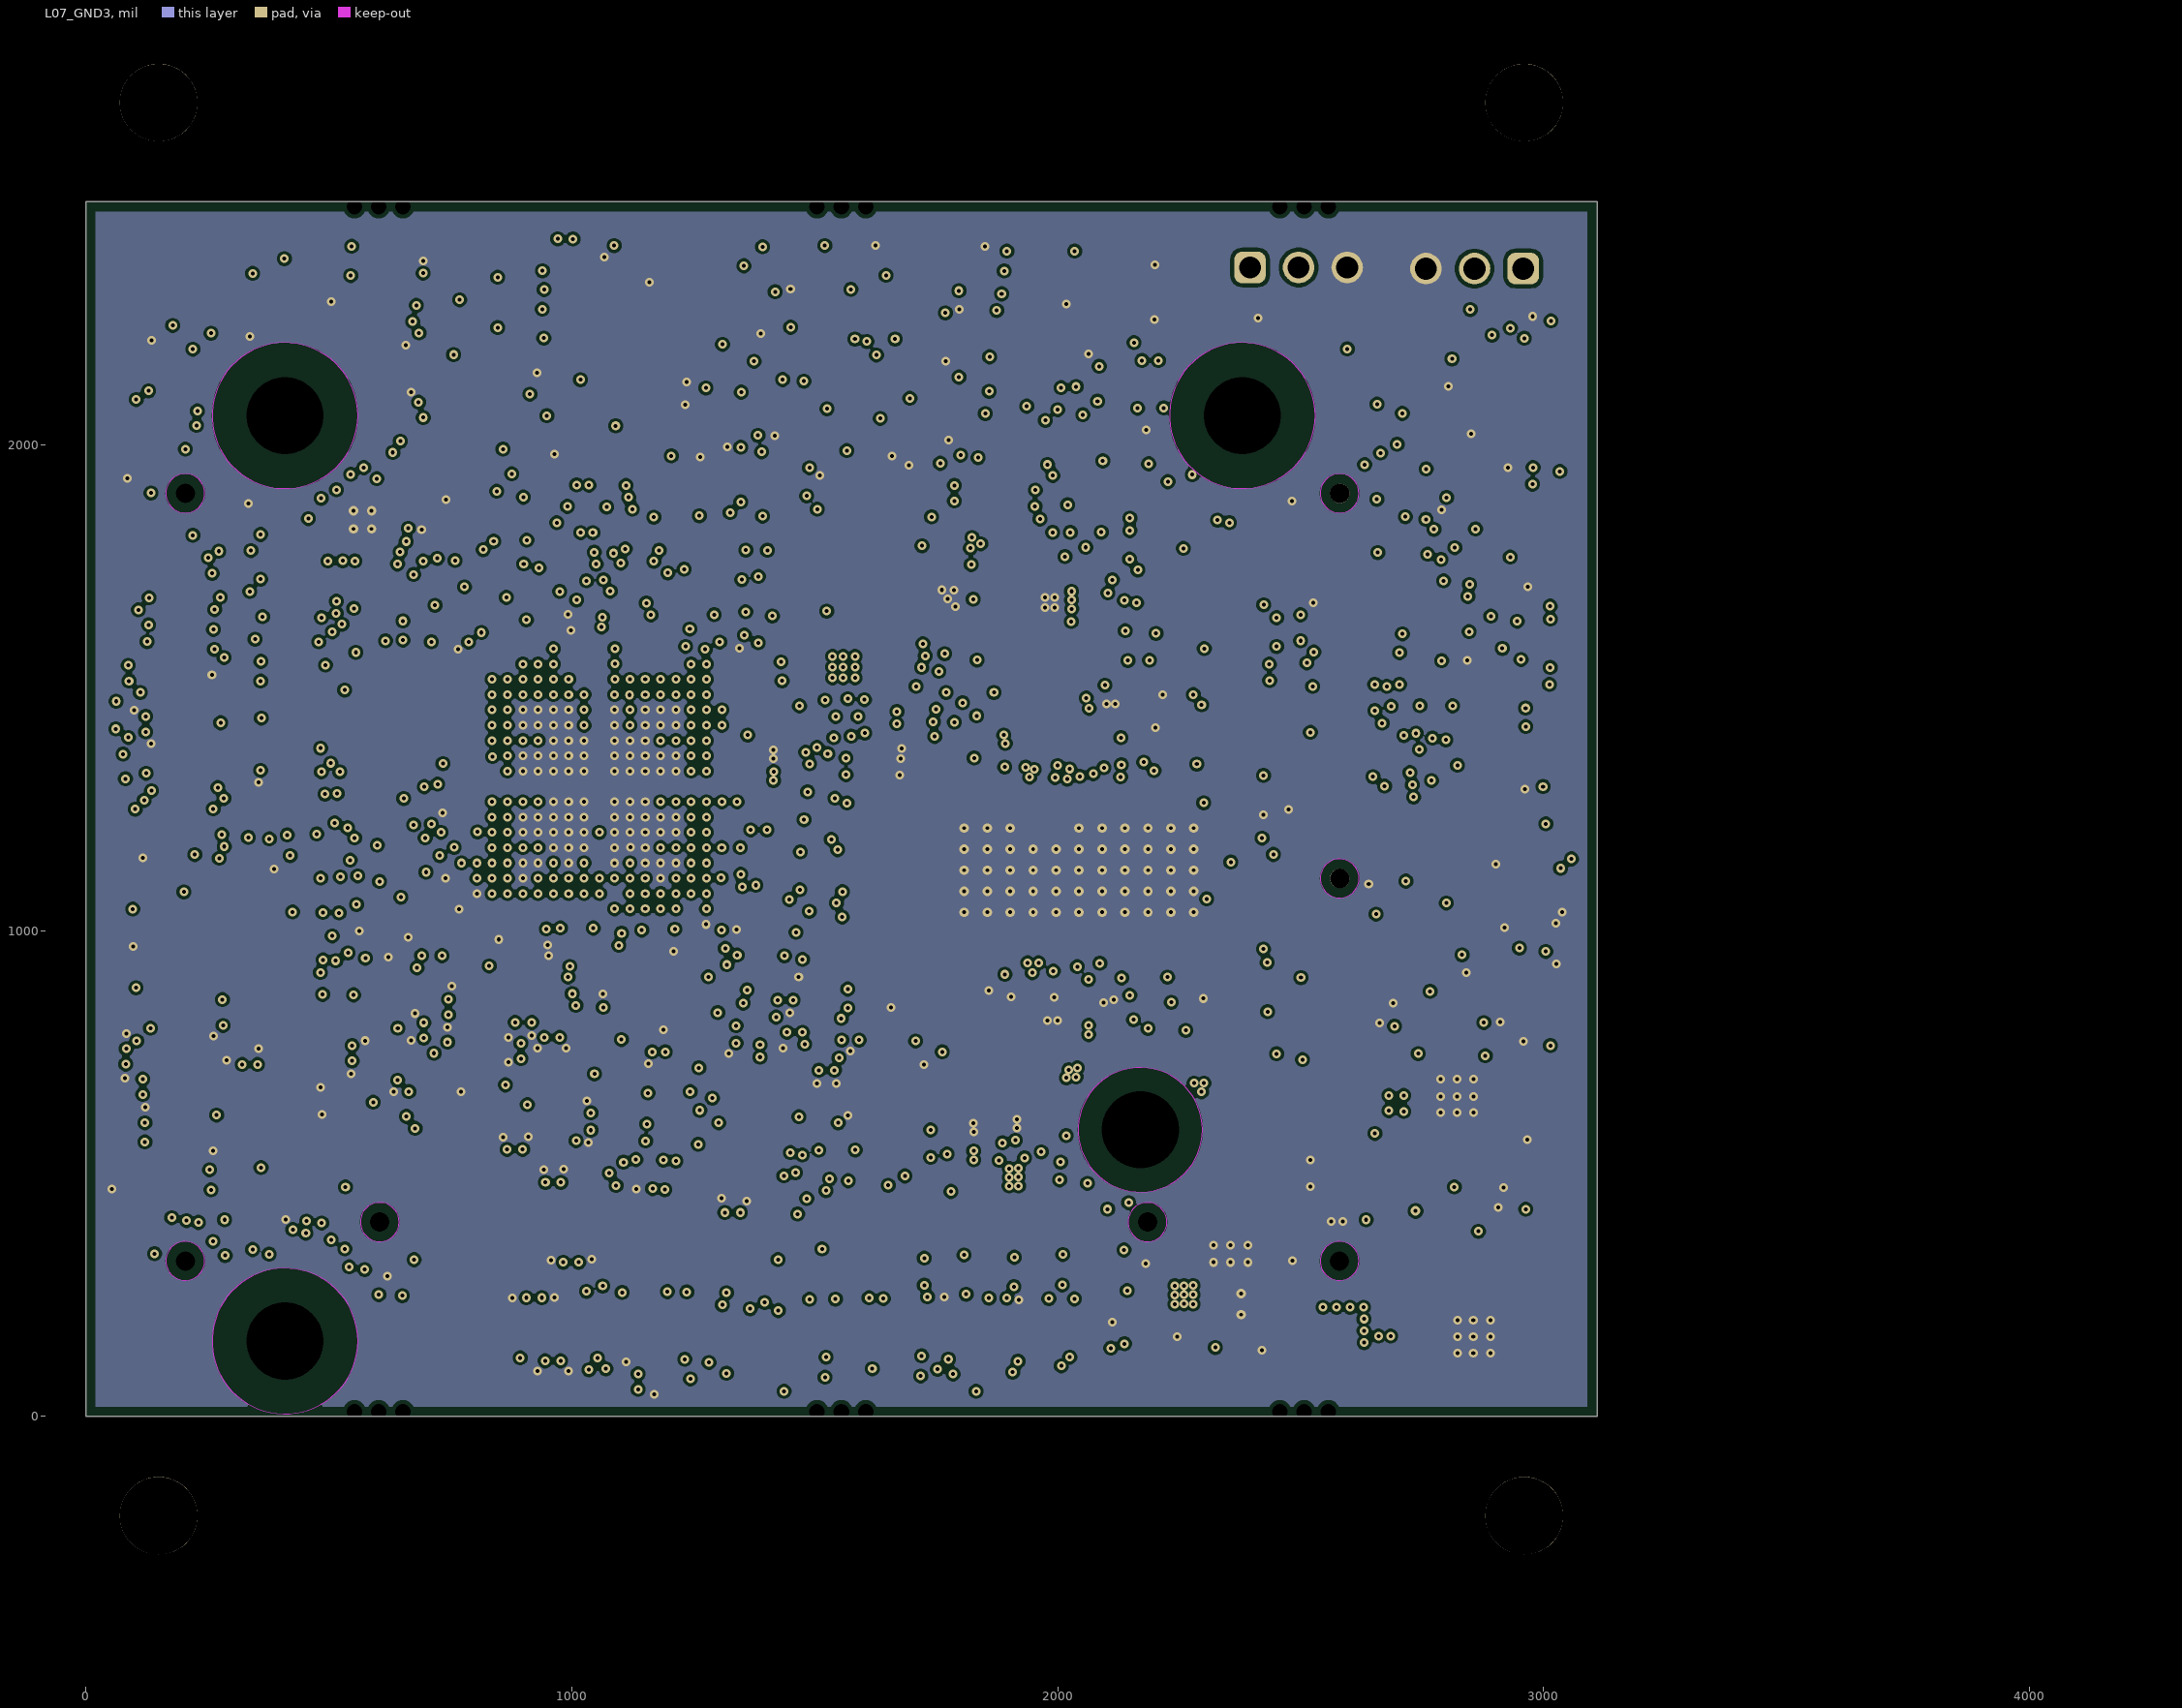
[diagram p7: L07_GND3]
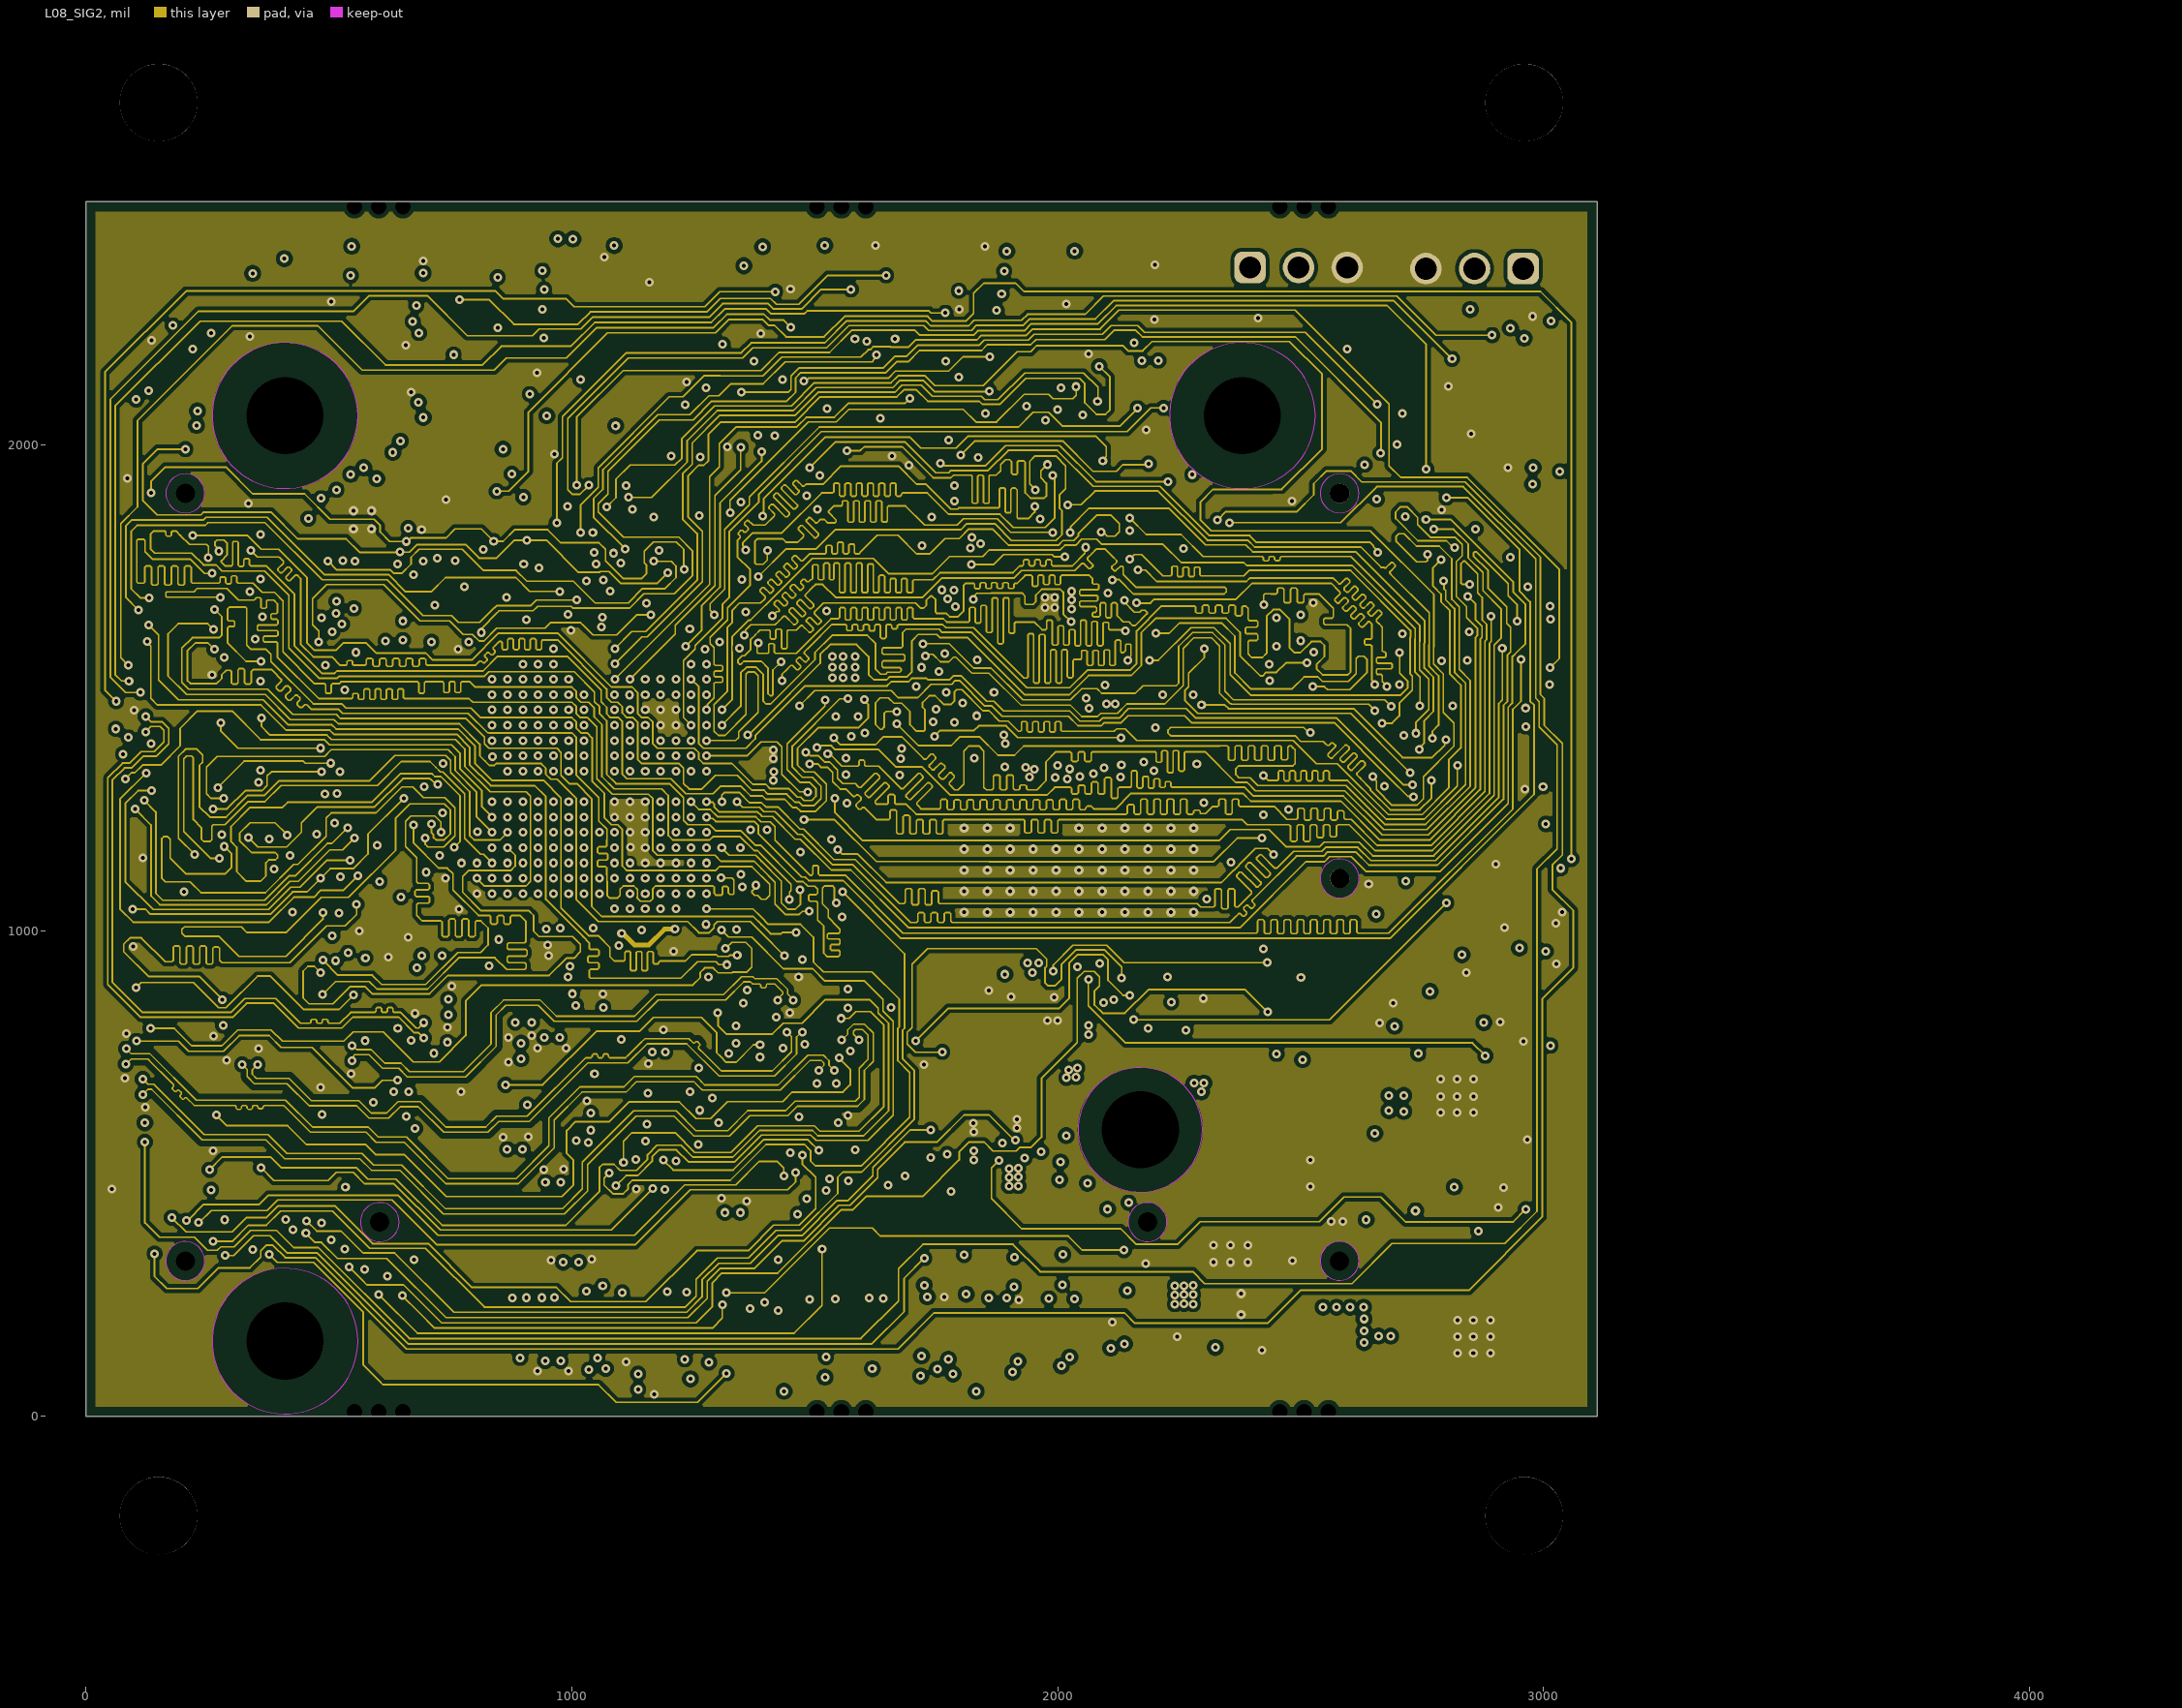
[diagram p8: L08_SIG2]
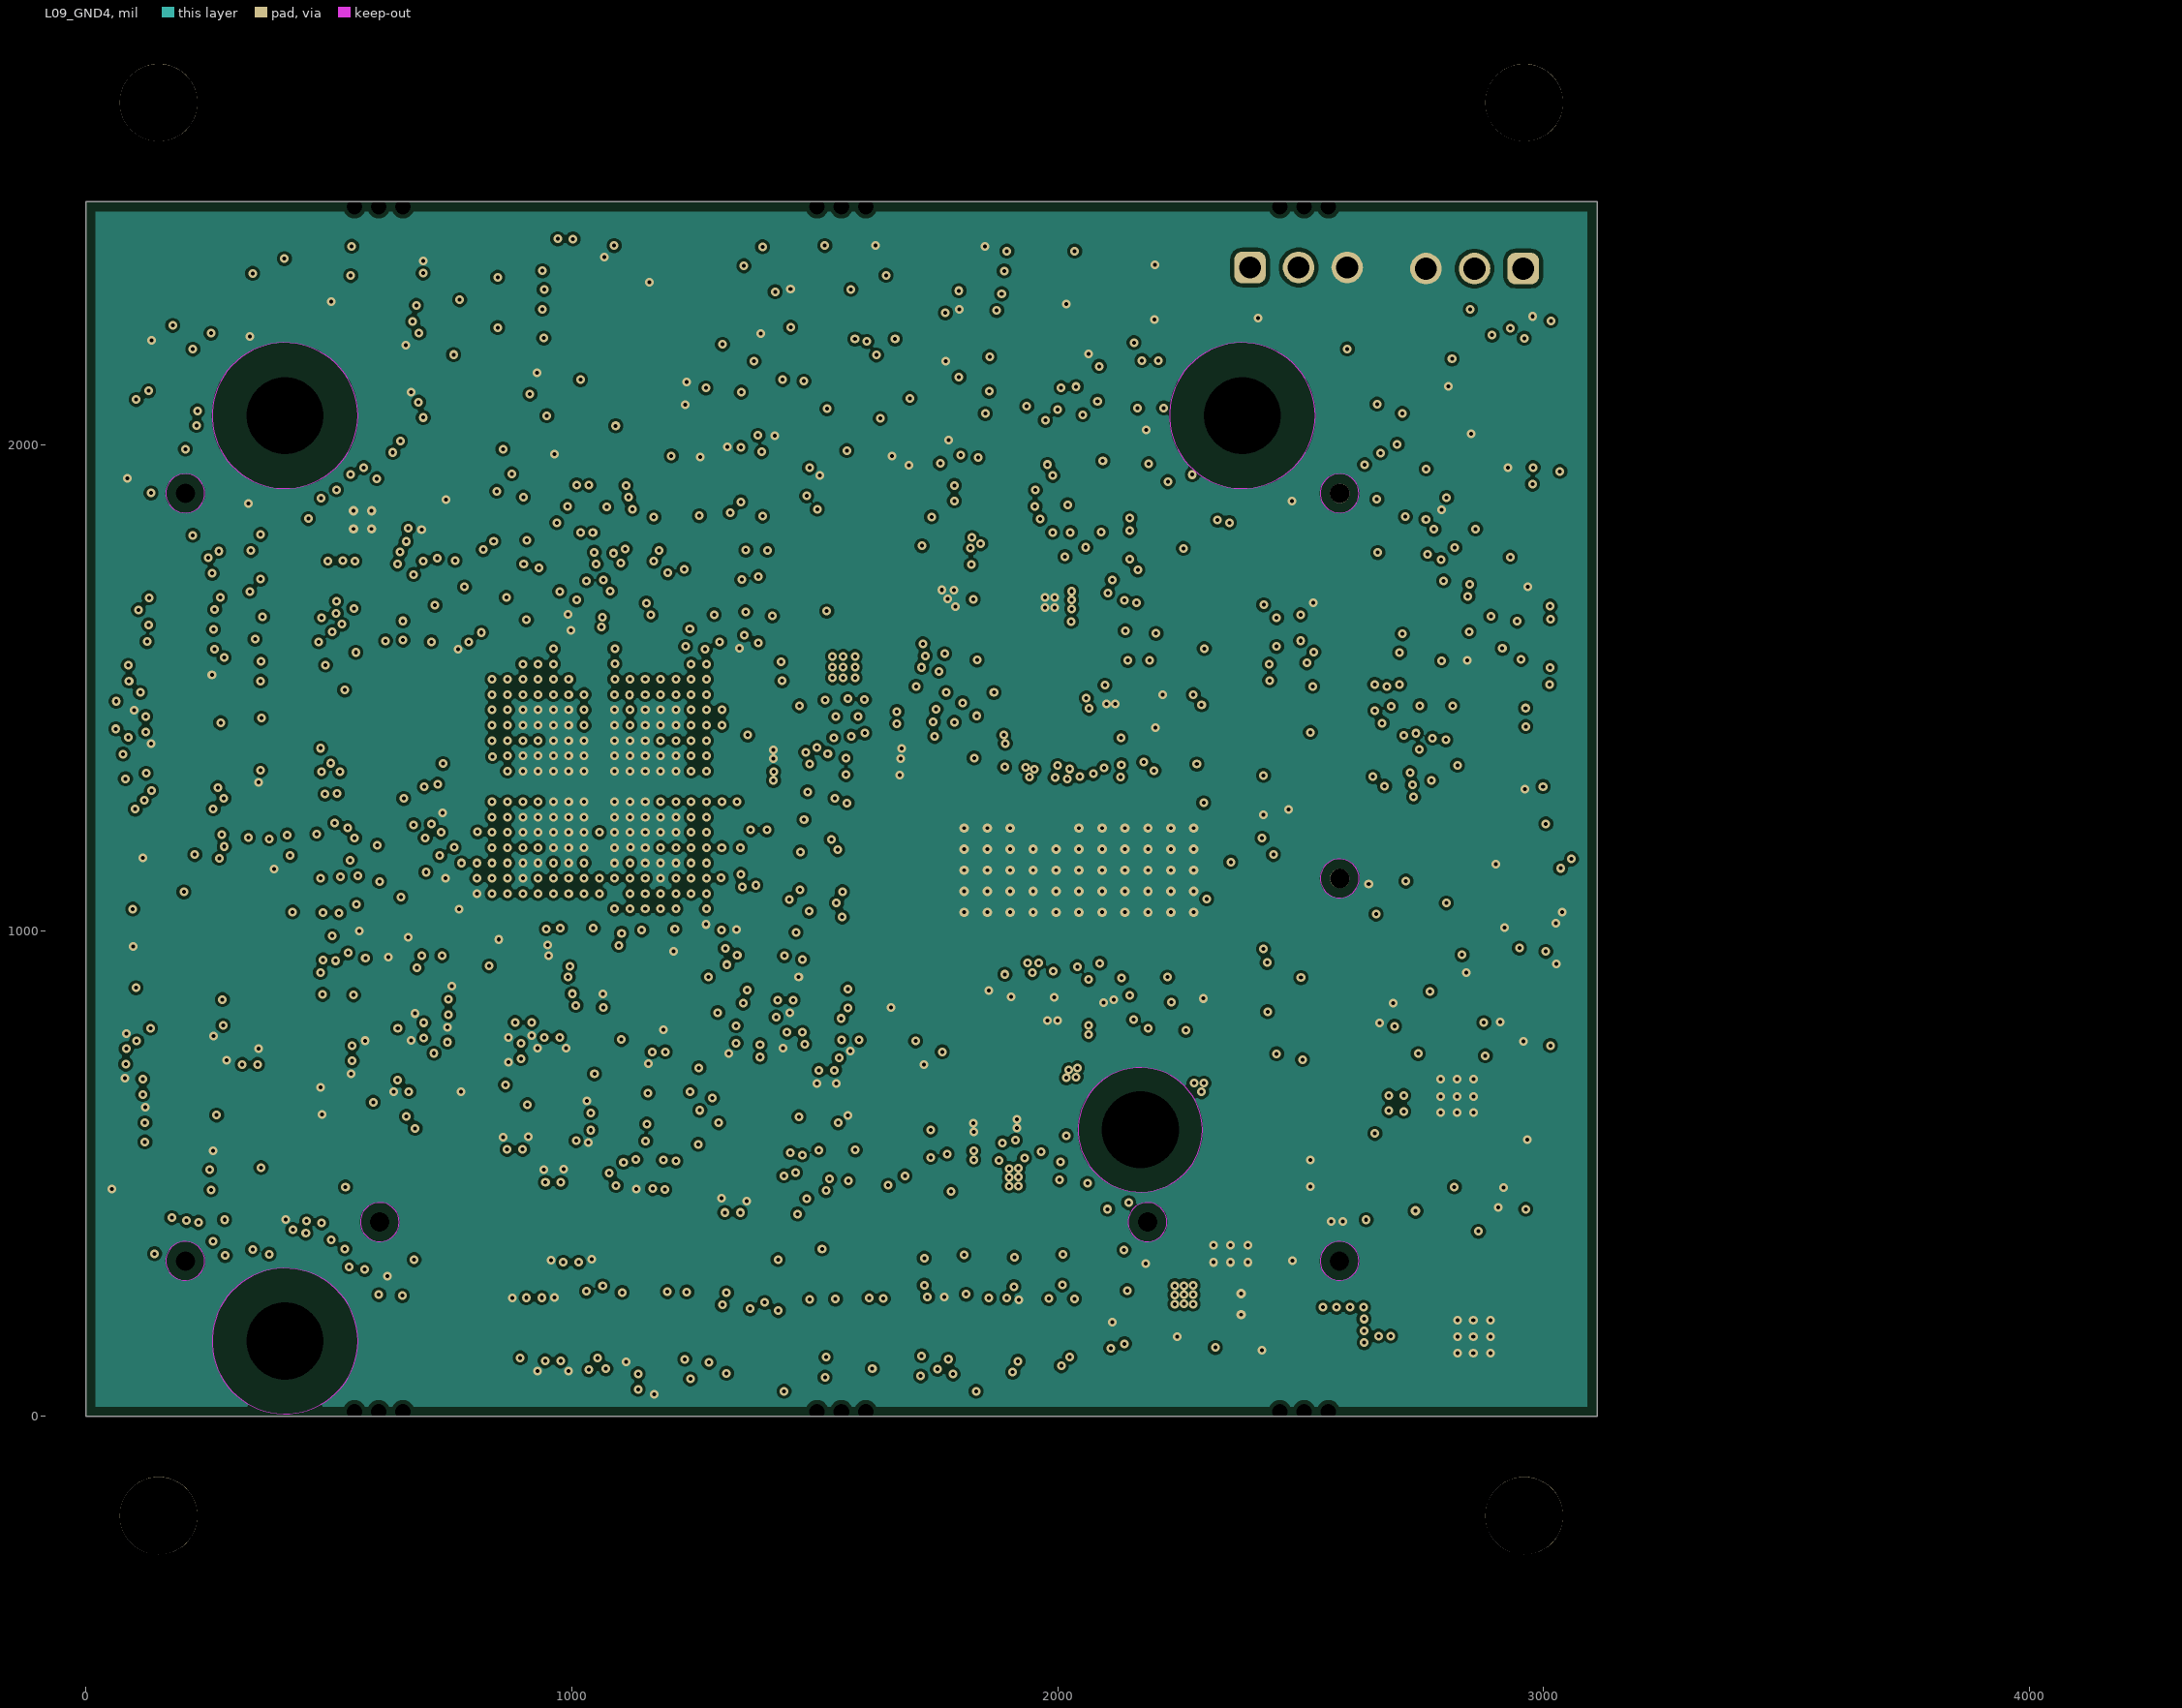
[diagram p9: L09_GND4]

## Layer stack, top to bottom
Top Solder: solder mask 2, Solder Resist, Dk 3.9
Top Layer: signal copper 1.85
Dielectric 2: prepreg 3.696, FR-4, Dk 3.79
L02_GND1: signal copper 1.26
Dielectric 4: prepreg 4, FR-4, Dk 4.4
L03_SIG1: signal copper 1.26
Dielectric 6: prepreg 6.594, FR-4, Dk 4.13
L04_GND2: signal copper 1.26
Dielectric 8: prepreg 5, FR-4, Dk 4.21
L05_PWR1: signal copper 1.26
Dielectric 10: prepreg 6.086, PP-006, Dk 4.13
Dielectric 1: prepreg 1.875, Composite dielectric, Dk 4.13
Dielectric 11: prepreg 6.086, PP-006, Dk 4.13
L06_PWR2: signal copper 1.26
Dielectric 9: prepreg 5, FR-4, Dk 4.21
L07_GND3: signal copper 1.26
Dielectric 7: prepreg 6.594, FR-4, Dk 4.13
L08_SIG2: signal copper 1.26
Dielectric 5: prepreg 4, FR-4, Dk 4.4
L09_GND4: signal copper 1.26
Dielectric 3: prepreg 3.696, FR-4, Dk 3.79
Bottom Layer: signal copper 1.85
Bottom Solder: solder mask 2, Solder Resist, Dk 3.9

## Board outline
0,0 0,2500 3110.24,2500 3110.24,0

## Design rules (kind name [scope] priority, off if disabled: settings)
BoardOutlineClearance [All] p1: gap=20 ignorepadtopadclearanceinfootprint=FALSE except(0: Arc-SplitContinuation Track-SplitContinuation SMDPad-SplitContinuation THPad-SplitContinuation Via-SplitContinuation Fill-SplitContinuation Poly-SplitContinuation Region-SplitContinuation Text-SplitContinuation)
Clearance Keepout [IsKeepOut] p1: gap=0 ignorepadtopadclearanceinfootprint=TRUE
Clearance Clearance_BGA [WithinRoom('BGA') vs InLayerClass('Outer layer')] p2: gap=8 ignorepadtopadclearanceinfootprint=TRUE except(3.4: Arc-Via Track-Via; 4.4: Arc-Arc Arc-Track Track-Track; 5: Arc-SMDPad Track-SMDPad SMDPad-Via; 6: Arc-Hole Track-Hole SMDPad-Hole THPad-Hole Via-Fill Via-Poly Via-Region Via-Hole Fill-Hole Poly-Hole Region-Hole Text-Text Text-Hole; 10: Fill-Fill Fill-Poly Fill-Region Poly-Poly Poly-Region Region-Region)
Clearance Clearance_BGA_innerlayer [WithinRoom('BGA') vs InLayerClass('Inner Sig')] p3: gap=8 ignorepadtopadclearanceinfootprint=TRUE except(4.8: Track-Via; 6: Arc-Arc Arc-Track Arc-SMDPad Arc-Via Arc-Hole Track-Track Track-SMDPad Track-Hole SMDPad-Via SMDPad-Hole THPad-Hole Via-Fill Via-Poly Via-Region Via-Hole Fill-Hole Poly-Hole Region-Hole Text-Text Text-Hole; 10: Fill-Fill Fill-Poly Fill-Region Poly-Poly Poly-Region Region-Region)
Clearance Clearance_power_LAYER [InLayerClass('PWR LAYER')] p4: gap=8 ignorepadtopadclearanceinfootprint=TRUE except(4: Via-Poly; 5: Poly-Region; 6: Arc-Arc Arc-Track Arc-SMDPad Arc-THPad Arc-Region Arc-Hole Track-Via Track-Region Track-Hole SMDPad-SMDPad SMDPad-Region SMDPad-Hole THPad-Region THPad-Hole Via-Fill Via-Region Via-Hole Fill-Region Fill-Hole Poly-Hole Region-Region Region-Hole Text-Text Text-Hole; 7: Arc-Via Track-SMDPad SMDPad-Via; 10: Fill-Fill Fill-Poly; 12: Track-THPad Track-Poly; 15: Poly-Poly; 20: Track-Track)
Clearance Clearance_GND [InLayerClass('GND LAYER')] p5: gap=6 ignorepadtopadclearanceinfootprint=TRUE except(5: Poly-Region; 7: Arc-Via Track-SMDPad SMDPad-Via; 8: Arc-Fill Arc-Poly Arc-Text Track-Fill Track-Text SMDPad-THPad SMDPad-Fill SMDPad-Poly SMDPad-Text THPad-THPad THPad-Via THPad-Fill THPad-Poly THPad-Text Via-Via Via-Text Fill-Text Poly-Text Region-Text; 10: Fill-Fill Fill-Poly; 12: Track-THPad Track-Poly; 20: Track-Track Poly-Poly)
Clearance Clearance_100E [InDifferentialPairClass('100E') vs InLayerClass('Electrical layer')] p6: gap=8 ignorepadtopadclearanceinfootprint=TRUE except(6: Arc-Arc Arc-Track Arc-SMDPad Arc-Via Arc-Region Arc-Hole Track-Via Track-Region Track-Hole SMDPad-Region SMDPad-Hole THPad-Region THPad-Hole Via-Region Via-Hole Fill-Region Fill-Hole Poly-Region Poly-Hole Region-Region Region-Hole Text-Text Text-Hole; 7: Track-SMDPad SMDPad-Via Via-Via; 12: Track-THPad Track-Poly; 15: Track-Track Fill-Fill Fill-Poly Poly-Poly)
Clearance Clearance_90E [InDifferentialPairClass('90E') vs InLayerClass('Electrical layer')] p7: gap=8 ignorepadtopadclearanceinfootprint=TRUE except(6: Arc-Arc Arc-Track Arc-SMDPad Arc-Region Arc-Hole Track-Via Track-Region Track-Hole SMDPad-Region SMDPad-Hole THPad-Region THPad-Hole Via-Fill Via-Region Via-Hole Fill-Region Fill-Hole Poly-Region Poly-Hole Region-Region Region-Hole Text-Text Text-Hole; 7: Arc-Via Track-SMDPad SMDPad-Via Via-Via; 12: Track-Track Track-THPad)
Clearance [All] p8: gap=8 ignorepadtopadclearanceinfootprint=TRUE except(4: Via-Region; 4.4: Track-Track; 6: Arc-Arc Arc-Track Arc-SMDPad Arc-THPad Arc-Via Arc-Hole Track-Via Track-Hole SMDPad-Hole THPad-Hole Via-Fill Via-Hole Fill-Hole Poly-Hole Region-Hole Text-Text Text-Hole; 7: Track-SMDPad SMDPad-Via Via-Via; 12: Track-THPad; 15: Fill-Fill Fill-Poly Fill-Region Poly-Poly Poly-Region Region-Region)
Clearance Clearance_samenet [All] p9: gap=4 ignorepadtopadclearanceinfootprint=TRUE except(0: Track-SMDPad Track-Via Track-Poly Track-Region Track-Hole SMDPad-Via SMDPad-Hole Via-Via Via-Hole; 2: Track-Track SMDPad-SMDPad)
DiffPairsRouting DIFF_100E [InDifferentialPairClass('100E')] p1: maxlimit=10 minlimit=7.15 mostfreqgap=10 toplayer_maxgap=7.15 toplayer_prefgap=7.15 toplayer_minwidth=4.25 toplayer_maxwidth=4.25 toplayer_prefwidth=4.25 midlayer1_mingap=10 midlayer1_minwidth=15 midlayer1_maxwidth=15 midlayer1_prefwidth=15 midlayer2_mingap=7.5 midlayer2_maxgap=7.5 midlayer2_prefgap=7.5 midlayer2_minwidth=3.2 midlayer2_maxwidth=3.2 midlayer2_prefwidth=3.2 midlayer3_mingap=10 midlayer3_minwidth=15 midlayer3_maxwidth=15 midlayer3_prefwidth=15 midlayer4_mingap=10 midlayer4_minwidth=15 midlayer4_maxwidth=15 midlayer4_prefwidth=15 midlayer5_mingap=7.5 midlayer5_maxgap=7.5 midlayer5_prefgap=7.5 midlayer5_minwidth=3.2 midlayer5_maxwidth=3.2 midlayer5_prefwidth=3.2 midlayer6_mingap=10 midlayer6_minwidth=15 midlayer6_maxwidth=15 midlayer6_prefwidth=15 midlayer7_mingap=10 midlayer7_minwidth=15 midlayer7_maxwidth=15 midlayer7_prefwidth=15 midlayer8_mingap=10 midlayer8_minwidth=15 midlayer8_maxwidth=15 midlayer8_prefwidth=15 bottomlayer_maxgap=7.15 bottomlayer_prefgap=7.15 bottomlayer_minwidth=4.25 bottomlayer_maxwidth=4.25 bottomlayer_prefwidth=4.25 maxuncoupledlength=1000
DiffPairsRouting DIFF_90E [InDifferentialPairClass('90E')] p2: maxlimit=6.22 minlimit=4.4 mostfreqgap=6.22 toplayer_maxgap=4.4 toplayer_prefgap=4.4 toplayer_minwidth=4.2 toplayer_maxwidth=4.2 toplayer_prefwidth=4.2 midlayer1_mingap=6.22 midlayer1_minwidth=5 midlayer1_maxwidth=5 midlayer1_prefwidth=5 midlayer2_mingap=6 midlayer2_maxgap=6 midlayer2_prefgap=6 midlayer2_minwidth=3.7 midlayer2_maxwidth=3.7 midlayer2_prefwidth=3.7 midlayer3_mingap=6.22 midlayer3_minwidth=5 midlayer3_maxwidth=5 midlayer3_prefwidth=5 midlayer4_mingap=6.22 midlayer4_minwidth=5 midlayer4_maxwidth=5 midlayer4_prefwidth=5 midlayer5_mingap=6 midlayer5_maxgap=6 midlayer5_prefgap=6 midlayer5_minwidth=3.7 midlayer5_maxwidth=3.7 midlayer5_prefwidth=3.7 midlayer6_mingap=6.22 midlayer6_minwidth=5 midlayer6_maxwidth=5 midlayer6_prefwidth=5 midlayer7_mingap=6.22 midlayer7_minwidth=5 midlayer7_maxwidth=5 midlayer7_prefwidth=5 midlayer8_mingap=6.22 midlayer8_minwidth=5 midlayer8_maxwidth=5 midlayer8_prefwidth=5 bottomlayer_maxgap=4.4 bottomlayer_prefgap=4.4 bottomlayer_minwidth=4.2 bottomlayer_maxwidth=4.2 bottomlayer_prefwidth=4.2 maxuncoupledlength=500
HoleSize [All] p1: absolutevalues=TRUE maxlimit=200 minlimit=1 maxpercent=80.000 minpercent=20.000
HoleToHoleClearance [InComponent('J3')] p1: gap=0 allowstackedmicrovias=FALSE
MatchedLengths DiffPair_MatchedLengths [InDifferentialPairClass('100E')] p1: tolerance=10 checknetsindiffpair=TRUE checkdiffpairvsdiffpair=FALSE checkxsignals=FALSE checkothers=FALSE
MatchedLengths OSPI [InxSignalClass('OSPI')] p2: tolerance=10 checknetsindiffpair=FALSE checkdiffpairvsdiffpair=TRUE checkxsignals=TRUE checkothers=TRUE
MatchedLengths ETHERNET1_RX [InxSignalClass('ETHERNET1_RX')] p3: tolerance=15 checknetsindiffpair=FALSE checkdiffpairvsdiffpair=TRUE checkxsignals=TRUE checkothers=TRUE
MatchedLengths ETHERNET1_TX [InNetClass('ETHERNET1_TX')] p4: tolerance=15 checknetsindiffpair=FALSE checkdiffpairvsdiffpair=TRUE checkxsignals=TRUE checkothers=TRUE
MatchedLengths ETHERNET2_TX [InxSignalClass('ETHERNET2_TX')] p5: tolerance=15 checknetsindiffpair=FALSE checkdiffpairvsdiffpair=TRUE checkxsignals=TRUE checkothers=TRUE
MatchedLengths ETHERNET2_RX [InxSignalClass('ETHERNET2_RX')] p6: tolerance=15 checknetsindiffpair=FALSE checkdiffpairvsdiffpair=TRUE checkxsignals=TRUE checkothers=TRUE
MatchedLengths ETHERNET3_RGMI_RX [InxSignalClass('ETHERNET3_RGMII_RX')] p7: tolerance=10 checknetsindiffpair=FALSE checkdiffpairvsdiffpair=TRUE checkxsignals=TRUE checkothers=TRUE
MatchedLengths ETHERNET3_RGMI_TX [InxSignalClass('ETHERNET3_RGMII_TX')] p8: tolerance=10 checknetsindiffpair=FALSE checkdiffpairvsdiffpair=TRUE checkxsignals=TRUE checkothers=TRUE
MatchedLengths MIPI [InxSignalClass('MIPI')] p9: tolerance=100 checknetsindiffpair=FALSE checkdiffpairvsdiffpair=TRUE checkxsignals=TRUE checkothers=TRUE
MatchedLengths FSI_TX [InxSignalClass('FSI_TX')] p10: tolerance=15 checknetsindiffpair=FALSE checkdiffpairvsdiffpair=TRUE checkxsignals=TRUE checkothers=TRUE
MatchedLengths FSI_RX [InNetClass('FSI_RX')] p11: tolerance=15 checknetsindiffpair=FALSE checkdiffpairvsdiffpair=TRUE checkxsignals=TRUE checkothers=TRUE
MinimumSolderMaskSliver MinimumSolderMaskSliver_exception [HasFootprint('CONN_QSH-060-01-L-D-A')] p1: minsoldermaskwidth=0.5
MinimumSolderMaskSliver [All] p2: minsoldermaskwidth=1
PolygonConnect [All] p1: connectstyle=Direct reliefconductorwidth=10 reliefentries=4 polygonreliefangle="90 Angle" airgapwidth=10
RoomDefinition PROC195_MCU_POWER_CAPS [InComponentClass('PROC195_MCU_POWER_CAPS')] p1: confinementstyle=ConfineIn formatcopy=TRUE lockcomponents=FALSE outline -995,-5470 1005,-5470 1005,-4470 -995,-4470
RoomDefinition BGA [False vs False] p2: confinementstyle=ConfineIn formatcopy=TRUE lockcomponents=FALSE outline 720.46,1629.65 1390.29,1629.65 1390.29,987.34 720.46,987.34
RoomDefinition PROC195_PMIC_BUCK [InComponentClass('PROC195_PMIC_BUCK')] p3: confinementstyle=ConfineIn formatcopy=TRUE lockcomponents=FALSE outline -995,-5470 1005,-5470 1005,-4470 -995,-4470
RoomDefinition PROC195_MIPI_Emulation_conn [InComponentClass('PROC195_MIPI_Emulation_conn')] p4: confinementstyle=ConfineIn formatcopy=TRUE lockcomponents=FALSE outline -995,-5470 1005,-5470 1005,-4470 -995,-4470
RoomDefinition PROC195_High_density_conn_1_2 [InComponentClass('PROC195_High_density_conn_1_2')] p5: confinementstyle=ConfineIn formatcopy=TRUE lockcomponents=FALSE outline -995,-5470 1005,-5470 1005,-4470 -995,-4470
RoomDefinition PROC195_High_density_conn3_4 [InComponentClass('PROC195_High_density_conn3_4')] p6: confinementstyle=ConfineIn formatcopy=TRUE lockcomponents=FALSE outline -995,-5470 1005,-5470 1005,-4470 -995,-4470
RoomDefinition PROC195_EVM_Hardware [InComponentClass('PROC195_EVM_Hardware')] p7: confinementstyle=ConfineIn formatcopy=TRUE lockcomponents=FALSE outline -995,-5470 1005,-5470 1005,-4470 -995,-4470
RoomDefinition PROC195_CLK_LED_CURRENT_MON_TEMP_CONN [InComponentClass('PROC195_CLK_LED_CURRENT_MON_TEMP_CONN')] p8: confinementstyle=ConfineIn formatcopy=TRUE lockcomponents=FALSE outline -995,-5470 1005,-5470 1005,-4470 -995,-4470
RoomDefinition PROC195_ADC [InComponentClass('PROC195_ADC')] p9: confinementstyle=ConfineIn formatcopy=TRUE lockcomponents=FALSE outline -995,-5470 1005,-5470 1005,-4470 -995,-4470
RoutingVias [All] p1: holewidth=8 width=19.68 viastyle="Through Hole" minholewidth=7.87 minwidth=18 maxholewidth=8 maxwidth=19.68
SilkToSilkClearance [All] p1: silktosilkclearance=1
SilkToSolderMaskClearance SilkToSolderMaskClearance_exeption [All] p1: minsilkscreentomaskgap=0 clearancetoexposedcopper=TRUE
SilkToSolderMaskClearance [All] p2: minsilkscreentomaskgap=3 clearancetoexposedcopper=TRUE
SolderMaskExpansion [All] p1: expansion=4 istentingtop=FALSE
UnRoutedNet [All] p1: checkbadconnections=TRUE
Width power [InNetClass('PWR')] p1: maxlimit=25 minlimit=4 preferedwidth=15 midlayer1_minwidth=10 midlayer1_maxwidth=10 midlayer1_prefwidth=10 midlayer3_minwidth=10 midlayer3_maxwidth=10 midlayer3_prefwidth=10 midlayer4_minwidth=10 midlayer4_maxwidth=10 midlayer4_prefwidth=10 midlayer6_minwidth=10 midlayer6_maxwidth=10 midlayer6_prefwidth=10 minimp=50.000000 maximp=50.000000 favimp=50.000000
Width 50_ohm [All] p2: maxlimit=20 minlimit=3.6 preferedwidth=10 toplayer_minwidth=5.6 toplayer_maxwidth=5.8 toplayer_prefwidth=5.8 midlayer1_minwidth=10 midlayer1_maxwidth=10 midlayer2_maxwidth=3.6 midlayer2_prefwidth=3.6 midlayer3_minwidth=10 midlayer3_maxwidth=10 midlayer4_minwidth=10 midlayer4_maxwidth=10 midlayer5_maxwidth=3.6 midlayer5_prefwidth=3.6 midlayer6_minwidth=10 midlayer6_maxwidth=10 midlayer7_minwidth=10 midlayer7_maxwidth=10 midlayer8_minwidth=10 bottomlayer_minwidth=5.8 bottomlayer_maxwidth=5.8 bottomlayer_prefwidth=5.8 minimp=50.000000 maximp=50.000000 favimp=50.000000
Width BGA_1 [WithinRoom('BGA')] p3: maxlimit=10 minlimit=5 preferedwidth=5.66
23 further rules are at their usual default settings.

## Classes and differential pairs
net class HIGH_SPEED: AM26x_FSIRX0_CLK AM26x_FSIRX0_DATA0 AM26x_FSIRX0_DATA1 AM26x_FSITX0_CLK AM26x_FSITX0_DATA0 AM26x_FSITX0_DATA1 AM26x_USB0_DM AM26x_USB0_DP MCU_PR0_PRU0_GPIO11 MCU_PR0_PRU0_GPIO12 MCU_PR0_PRU0_GPIO13 MCU_PR0_PRU0_GPIO14 MCU_PR0_PRU0_GPIO16 MCU_PR0_PRU1_GPIO11 MCU_PR0_PRU1_GPIO12 MCU_PR0_PRU1_GPIO13 MCU_PR0_PRU1_GPIO14 MCU_PR0_PRU1_GPIO16 MCU_SPI0_CLK MCU_SPI0_D0 MCU_SPI0_D1 MIPI_TRC_CLK[0] MIPI_TRC_DATA_00 MIPI_TRC_DATA_01 MIPI_TRC_DATA_02 MIPI_TRC_DATA_03 MIPI_TRC_DATA_04 MIPI_TRC_DATA_05 MIPI_TRC_DATA_06 MIPI_TRC_DATA_07 MIPI_TRC_DATA_08 MIPI_TRC_DATA_09 MIPI_TRC_DATA_30 MIPI_TRC_DATA_31 MIPI_TRC_DATA_32 MIPI_TRC_DATA_33 MIPI_TRC_DATA_34 MIPI_TRC_DATA_35 MIPI_TRC_DATA_36 OSPI0_CLK OSPI0_CSN0 OSPI0_D0 OSPI0_D1 OSPI0_D2 OSPI0_D3 OSPI0_D4 OSPI0_D5 OSPI0_D6 OSPI0_D7 OSPI0_DQS PR0_PRU0_GPIO0 PR0_PRU0_GPIO1 PR0_PRU0_GPIO2 PR0_PRU0_GPIO3 PR0_PRU0_GPIO4 PR0_PRU0_GPIO6 PR0_PRU0_GPIO9 PR0_PRU0_GPIO11 PR0_PRU0_GPIO12 PR0_PRU0_GPIO13 PR0_PRU0_GPIO14 PR0_PRU0_GPIO15 PR0_PRU0_GPIO16 PR0_PRU1_GPIO0 PR0_PRU1_GPIO1 PR0_PRU1_GPIO2 PR0_PRU1_GPIO3 PR0_PRU1_GPIO4 PR0_PRU1_GPIO6 PR0_PRU1_GPIO9 PR0_PRU1_GPIO11 PR0_PRU1_GPIO12 PR0_PRU1_GPIO13 PR0_PRU1_GPIO14 PR0_PRU1_GPIO15 PR0_PRU1_GPIO16 R_MCU_GPIO119 R_MCU_GPIO120 R_OSPI0_D0 R_OSPI0_D1 R_OSPI0_D2 R_OSPI0_D3 R_OSPI0_D4 R_OSPI0_D5 R_OSPI0_D6 R_OSPI0_D7 R_OSPI0_DQS R_PR0_PRU1_GPIO0 R_PR0_PRU1_GPIO1 R_PR0_PRU1_GPIO2 R_PR0_PRU1_GPIO3 R_PR0_PRU1_GPIO4 R_PR0_PRU1_GPIO5 R_PR0_PRU1_GPIO6 R_PR0_PRU1_GPIO8 R_PR0_PRU1_GPIO9 R_PR0_PRU1_GPIO10 R_PR0_PRU1_GPIO11 R_PR0_PRU1_GPIO12 R_PR0_PRU1_GPIO13 R_PR0_PRU1_GPIO14 R_PR0_PRU1_GPIO15 R_PR0_PRU1_GPIO16 R_RGMII1_RD0 R_RGMII1_RD1 R_RGMII1_RD2 R_RGMII1_RD3 R_RGMII1_RX_CTL R_RGMII1_TD0 R_RGMII1_TD1 R_RGMII1_TD2 R_RGMII1_TD3 R_RGMII1_TX_CTL R_RGMII1_TXC RGMII1_RD0 RGMII1_RD1 RGMII1_RD2 RGMII1_RD3 RGMII1_RX_CTL RGMII1_RXC RGMII1_TD0 RGMII1_TD1 RGMII1_TD2 RGMII1_TD3 RGMII1_TX_CTL RGMII1_TXC
net class JTAG: AM26x_TCK AM26x_TDI AM26x_TDO AM26x_TMS TCK TDI TDO TMS
net class FSI_RX: AM26x_FSIRX0_CLK AM26x_FSIRX0_DATA0 AM26x_FSIRX0_DATA1
differential pair class 90E: AM26x_USB USB_R
differential pair class 100E: AM26x_ADC0_2 AM26x_ADC0_3 AM26x_ADC1_1 AM26x_ADC1_2 AM26x_ADC2_1 AM26x_ADC2_2 AM26x_ADC3_1 AM26x_ADC3_2 AM26x_ADC4_1 AM26x_ADC4_2 AM26x_ADC_R0_1 AM26x_ADC_R0_2 AM26x_ADC_R1_1 AM26x_ADC_R1_2 R_ADC3_1 R_ADC3_2 R_ADC4_1 R_ADC4_2
net class ETHERNET1_TX: PR0_PRU0_GPIO0 PR0_PRU0_GPIO1 PR0_PRU0_GPIO2 PR0_PRU0_GPIO3 PR0_PRU0_GPIO4 PR0_PRU0_GPIO6 PR0_PRU0_GPIO9
net class PWR: 1V8_LDO4 3V3_LDO2 5V0_LDO3 +1V2 ADC_VREFHI_G0_G1 ADC_VREFHI_G2_G3 AM26x_VREFHI1 AM26x_VREFHI2 AM26x_VREFLO BOOST_COMP BOOST_EN BOOST_FB BUCK_FB CLOCK_VDD DAC_VREF EXT_VREF1 EXT_VREF1_SW EXT_VREF2 EXT_VREF2_SW GND INT_VREF1 INT_VREF2 NetL2_1 NetR9_2 NetR35_2 NetS2_3 PLDO1_OUT PLDO2_OUT R_AM26x_VREFHI_G3 VCC_1V2 VCC_6V0 VDD_IO_3V3 VDDA18_LDO_1V8 VDDA18_OSC_PLL_AM26x VDDA_3V3 VDDS18_LDO_1V8 VMAIN_5V0 VMAIN_5V0_IN VMAIN_12V0 VPP_1V8 VREF_DEBUG VSYS_3V3_LDO1
component class "PROC195_SDFM, JTAG": C131 C174 R76 R80 R81 R129 R132 R157 R158 R162 R165 R166 R168 R214 R215 R266 R267 R268 R269 R270 R271 U12 U25
component class PROC195_RESET_CIRCUIT: C155 C156 C157 C158 C159 C160 C161 R41 R53 R84 R138 R245 R246 R247 R248 R249 R250 R251 R252 R253 R254 R255 R256 R257 R258 R259 R311 R312 SW2 SW3 SW4 TP18 U4 U21 U23 U24
component class PROC195_PMIC_BUCK: C58 C59 C60 C63 C64 C65 C66 C67 C68 C69 C70 C71 C72 C73 C74 C81 C82 C86 C87 C88 C89 C90 C91 C93 C94 C95 C97 C98 C99 C101 C104 C107 C109 C111 C112 C113 C114 C132 C167 C168 C169 J8 J9 L1 L2 R14 R15 R16 R17 R18 R19 R20 R21 R22 R23 R24 R25 R27 R28 R29 R30 R32 R33 R35 R37 TP2 TP3 TP4 TP5 TP6 TP7 TP8 TP9 TP10 TP11 TP12 TP13 TP14 TP15 U2 U3
component class PROC195_OSPI_BOOTMODE: C75 C76 C78 C137 C138 C139 C140 C141 R38 R39 R140 R174 R175 R176 R177 R178 R179 R180 R181 R182 R183 R184 R185 R186 R187 R189 R191 R193 R195 R196 R197 R198 R199 R200 R201 R202 R203 R204 R205 R206 R207 R208 R211 R212 R217 R218 R219 R220 R221 R222 R223 R224 R225 R226 R227 R228 R229 R230 R231 R232 R237 SW1 U15 U16 U17
component class PROC195_MIPI_Emulation_conn: J5 J7 R26 R31 R40 R59 R60 R61 R62 R63 R64 R65 R86 R87 R88 R89 R90 R91 R92 R93 R94 R95 R96 R97 R98 R99 R100 R101 R102 R103 R216 R260 R313 R314 R315 R316
component class PROC195_MCU_POWER_CAPS: C1 C2 C3 C4 C5 C6 C7 C8 C9 C10 C11 C12 C13 C14 C15 C16 C17 C18 C19 C20 C21 C22 C23 C24 C25 C26 C27 C28 C29 C30 C31 C32 C33 C34 C35 C36 C37 C38 C39 C40 C41 C42 C43 C44 C45 C46 C47 C48 C49 C50 C51 C52 C53 C54 C55 C57 FB1 FB2 R9 R10 R11 R12 R13 R148 TP1
component class PROC195_High_density_conn_1_2: J1 J2 R1 R2 R74
component class PROC195_High_density_conn3_4: J3 R5 R8
component class PROC195_EVM_Hardware: !PCB1 FID1 FID2 FID3 FID4 FID5 FID6 Logo1 Logo2 Logo3 Logo4 MH1 MH2 MH3 MH4 ZZ1 ZZ2 ZZ3 ZZ4
component class PROC195_EPWM: R4 R79 R83 R85 R104 R105 R106 R107 R108 R109 R110 R111 R112 R113 R114 R115 R116 R117 R118 R119 R120 R121 R122 R123 R124 R125 R126 R127 R128 R130 R131 R133 R134 R135 R136 R137 R139 R141 R142 R143 R144 R145 R146 R147 R149 R150 R151 R152 R153 R154 R155 R156 R159 R161 R163 R164 R167 R169 R170 R171 R172 R173 R239 R261 R262 R263 R282
component class PROC195_DAC: C105 C152 C153 C154 R6 R7 R233 R234 R235 R236 R238 R264 R283 R284 R285 R286 R287 R288 R289 R290 R291 R292 R293 R294 R295 R296 R297 R298 R299 R300 R301 R302 R303 R310 S2 U13 U20
component class PROC195_CLK_LED_CURRENT_MON_TEMP_CONN: C77 C115 C116 C117 C118 C119 C120 C121 C129 C130 D2 D3 FB3 R3 R36 R43 R44 R46 R47 R48 R49 R50 R51 R52 R54 R55 R56 R66 R67 R69 R70 R71 R210 R213 TP16 TP17 U5 U6 U7 U8 U9 U10 Y1
component class PROC195_ADC: C56 C122 C123 C124 C125 C126 C127 C128 MS R73 R75 R77 R78 R240 R241 R242 R243 R244 R272 R273 R274 R275 R276 R277 R278 R304 R305 R306 R307 R308 R309 S1 S4 U1 U11 U18
component class PROC195__FET_BOOST_REG: C61 C62 C79 C80 C83 C84 C85 C92 C96 C100 C102 C103 D4 D5 D6 D7 D8 D9 D10 L3 Q2 Q3 Q4 R34 R42 R45 R57 R58 R68 R72 R82 R160 R188 R190 R192 R194 R209 R265 R279 R280 R281 U14 U22
pad class pad1: MH1-1
differential pair R_ADC4_2: +R_ADC4_AIN2_P -R_ADC4_AIN3_N
differential pair R_ADC4_1: +R_ADC4_AIN0_P -R_ADC4_AIN1_N
differential pair R_ADC3_2: +R_ADC3_AIN2_P -R_ADC3_AIN3_N
differential pair R_ADC3_1: +R_ADC3_AIN0_P -R_ADC3_AIN1_N
differential pair USB_R: +NetR168_2 -NetR165_2
differential pair AM26x_USB: +AM26x_USB0_DP -AM26x_USB0_DM
differential pair VCC_1V2: +VCC_1V2_P -VCC_1V2_N
differential pair VDD_IO_3V3: +VDD_IO_3V3_P -VDD_IO_3V3_N
differential pair AM26x_ADC_R1_2: +AM26x_ADC_R1_AIN2_P -AM26x_ADC_R1_AIN3_N
differential pair AM26x_ADC_R1_1: +AM26x_ADC_R1_AIN0_P -AM26x_ADC_R1_AIN1_N
differential pair AM26x_ADC_R0_2: +AM26x_ADC_R0_AIN2_P -AM26x_ADC_R0_AIN3_N
differential pair AM26x_ADC_R0_1: +AM26x_ADC_R0_AIN0_P -AM26x_ADC_R0_AIN1_N
differential pair AM26x_ADC4_2: +AM26x_ADC4_AIN2_P -AM26x_ADC4_AIN3_N
differential pair AM26x_ADC4_1: +AM26x_ADC4_AIN0_P -AM26x_ADC4_AIN1_N
differential pair AM26x_ADC3_2: +AM26x_ADC3_AIN2_P -AM26x_ADC3_AIN3_N
differential pair AM26x_ADC3_1: +AM26x_ADC3_AIN0_P -AM26x_ADC3_AIN1_N
differential pair AM26x_ADC2_2: +AM26x_ADC2_AIN2_P -AM26x_ADC2_AIN3_N
differential pair AM26x_ADC2_1: +AM26x_ADC2_AIN0_P -AM26x_ADC2_AIN1_N
differential pair AM26x_ADC1_2: +AM26x_ADC1_AIN2_P -AM26x_ADC1_AIN3_N
differential pair AM26x_ADC1_1: +AM26x_ADC1_AIN0_P -AM26x_ADC1_AIN1_N
differential pair AM26x_ADC0_3: +AM26x_ADC0_AIN4_P -AM26x_ADC0_AIN5_N
differential pair AM26x_ADC0_2: +AM26x_ADC0_AIN2_P -AM26x_ADC0_AIN3_N

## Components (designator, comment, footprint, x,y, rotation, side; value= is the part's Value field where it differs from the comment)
C1 "CL10A335KP8NNNC" FP-CL10A335KP8NNNC_0603-MFG 1384.26,1335.51 r90 bottom value=3.3µF
C2 "CL10A335KP8NNNC" FP-CL10A335KP8NNNC_0603-MFG 1341.65,1335.8 r90 bottom value=3.3µF
C3 "CL10A335KP8NNNC" FP-CL10A335KP8NNNC_0603-MFG 771.55,1293.24 r270 bottom value=3.3µF
C4 "GRM033Z71C104KE14D" 0201L 910.4,1406.65 r90 bottom value=0.1uF
C5 "CL10A335KP8NNNC" FP-CL10A335KP8NNNC_0603-MFG 1619.54,1325.33 r0 bottom value=3.3µF
C6 "CL10A335KP8NNNC" FP-CL10A335KP8NNNC_0603-MFG 1619.54,1325.33 r0 top value=3.3µF
C7 "CL10A335KP8NNNC" FP-CL10A335KP8NNNC_0603-MFG 1620.12,1373.8 r0 top value=3.3µF
C8 "GRM033Z71C104KE14D" 0201L 883.93,1370.68 r0 bottom value=0.1uF
C9 "GRM033Z71C104KE14D" 0201L 1230.38,1244.7 r180 bottom value=0.1uF
C10 "GRM033Z71C104KE14D" 0201L 1230.38,1370.68 r180 bottom value=0.1uF
C11 "GRM033Z71C104KE14D" 0201L 1228.52,1124.48 r135 bottom value=0.1uF
C12 "GRM033Z71C104KE14D" 0201L 883.93,1150.21 r0 bottom value=0.1uF
C13 "GRM033Z71C104KE14D" 0201L 977.65,1470.08 r225 bottom value=0.1uF
C14 "GRM033Z71C104KE14D" 0201L 1166.96,1469.43 r315 bottom value=0.1uF
C15 "GRM033Z71C104KE14D" 0201L 941.9,1406.65 r90 bottom value=0.1uF
C16 "GRM033Z71C104KE14D" 0201L 1009.36,1411.67 r180 bottom value=0.1uF
C17 "GRM033Z71C104KE14D" 0201L 1009.36,1443.17 r180 bottom value=0.1uF
C18 "GRM033Z71C104KE14D" 0201L 1135.35,1443.17 r0 bottom value=0.1uF
C19 "GRM033Z71C104KE14D" 0201L 1103.85,1411.67 r180 bottom value=0.1uF
C20 "GRM033Z71C104KE14D" 0201L 1171.87,1407.2 r90 bottom value=0.1uF
C21 "GRM033Z71C104KE14D" 0201L 1203.36,1407.2 r90 bottom value=0.1uF
C22 "GRM033Z71C104KE14D" 0201L 919.9,1249.72 r270 bottom value=0.1uF
C23 "GRM033Z71C104KE14D" 0201L 747.89,1139.71 r270 bottom value=0.1uF
C24 "GRM033Z71C104KE14D" 0201L 901.08,1298.63 r90 bottom value=0.1uF
C25 "GRM033Z71C104KE14D" 0201L 888.4,1186.73 r90 bottom value=0.1uF
C26 "GRM033Z71C104KE14D" 0201L 919.9,1186.73 r90 bottom value=0.1uF
C27 "GRM033Z71C104KE14D" 0201L 1171.87,1186.73 r90 bottom value=0.1uF
C28 "CL10A335KP8NNNC" FP-CL10A335KP8NNNC_0603-MFG 1049.49,902.76 r0 bottom value=3.3µF
C29 "CL10A335KP8NNNC" FP-CL10A335KP8NNNC_0603-MFG 1044.45,983.66 r180 bottom value=3.3µF
C30 "GRM033Z71C104KE14D" 0201L 979.81,947.78 r180 bottom value=0.1uF
C31 "GRM033Z71C104KE14D" 0201L 1135.9,1150.21 r0 bottom value=0.1uF
C32 "GRM033Z71C104KE14D" 0201L 951.39,1155.23 r90 bottom value=0.1uF
C33 "GRM033Z71C104KE14D" 0201L 1014.39,1155.23 r90 bottom value=0.1uF
C34 "GRM033Z71C104KE14D" 0201L 931.08,1298.39 r90 bottom value=0.1uF
C35 "GRM033Z71C104KE14D" 0201L 1203.36,1186.73 r90 bottom value=0.1uF
C36 "GRM033Z71C104KE14D" 0201L 1167.39,1276.19 r180 bottom value=0.1uF
C37 "GRM033Z71C104KE14D" 0201L 1212.11,1297.15 r90 bottom value=0.1uF
C38 "CL10A335KP8NNNC" FP-CL10A335KP8NNNC_0603-MFG 1441.08,1340.36 r90 top value=3.3µF
C39 "CL10A335KP8NNNC" FP-CL10A335KP8NNNC_0603-MFG 1023.2,1563.89 r180 bottom value=3.3µF
C40 "CL10A335KP8NNNC" FP-CL10A335KP8NNNC_0603-MFG 797.81,1014.19 r180 bottom value=3.3µF
C41 "GRM033Z71C104KE14D" 0201L 836.65,1301.15 r270 bottom value=0.1uF
C42 "GRM033Z71C104KE14D" 0201L 1077.38,1470.19 r270 bottom value=0.1uF
C43 "GRM033Z71C104KE14D" 0201L 808.13,1301.15 r270 bottom value=0.1uF
C44 "GRM033Z71C104KE14D" 0201L 1230.75,1186.99 r135 bottom value=0.1uF
C45 "GRM033Z71C104KE14D" 0201L 883.93,1244.7 r0 bottom value=0.1uF
C46 "GRM033Z71C104KE14D" 0201L 809.59,1054.53 r180 bottom value=0.1uF
C47 "GRM033Z71C104KE14D" 0201L 919.9,1470.19 r270 bottom value=0.1uF
C48 "GRM033Z71C104KE14D" 0201L 1230.38,1465.17 r180 bottom value=0.1uF
C49 "GRM155R61A475MEAAD" 0402L 663.35,1026.54 r270 bottom value=4.7uF
C50 "GRM033Z71C104KE14D" 0201L 1103.97,1122.97 r135 bottom value=0.1uF
C51 "GRM033Z71C104KE14D" 0201L 982.89,1123.74 r90 bottom value=0.1uF
C52 "GRM033Z71C104KE14D" 0201L 919.9,1123.74 r90 bottom value=0.1uF
C53 "GRM033Z71C104KE14D" 0201L 883.47,1118.22 r0 bottom value=0.1uF
C54 "GRM033Z71C104KE14D" 0201L 694.96,1030.37 r270 bottom value=0.1uF
C55 "GRM033Z71C104KE14D" 0201L 1304.96,1334.12 r90 bottom value=0.1uF
C56 "GRM155R71H104KE14D" FP-GRM155R71H104KE14D_0402-MFG 1286.71,2182.91 r270 bottom value=100nF
C57 "GRM033Z71C104KE14D" 0201L 661.15,886.43 r270 bottom value=0.1uF
C58 "GRM31CR61E476ME44K" FP-GRM31CR61E476ME44K_1206-MFG 1871.03,658.09 r270 top value=47µF
C59 "GRM21BR61H106KE43L" FP-GRM21BR61H106KE43L_0805-MFG 1790.05,661.04 r90 top value=10µF
C60 "GRM21BR61H106KE43L" FP-GRM21BR61H106KE43L_0805-MFG 1790.05,661.04 r90 bottom value=10µF
C61 "GRM155R71E104KE14D" 0402 2703.84,380.4 r180 top value=0.1uF
C62 "GRM31CR61E476ME44K" FP-GRM31CR61E476ME44K_1206-MFG 2583.88,122.9 r270 top value=47µF
C63 "GRM155R61E225KE11D" "FP-GRM155R61E225KE11D_0402 (1005 metric)-MFG" 1957.23,787.29 r0 top value=2.2µF
C64 "GRM155R61E225KE11D" "FP-GRM155R61E225KE11D_0402 (1005 metric)-MFG" 1869.06,827.42 r90 bottom value=2.2µF
C65 "GRM1555C1H102JA01D" 0402 1953.29,839.29 r180 bottom value=1000pF
C66 "GRM1555C1H102JA01D" 0402 1953.87,887.68 r180 top value=1000pF
C67 "GRM155R71E104KE14D" 0402 1869.77,822.56 r90 top value=0.1uF
C68 "GRM155R71E104KE14D" 0402 1953.87,839.29 r0 top value=0.1uF
C69 "GRM155R71E104KE14D" 0402 1953.29,787.29 r0 bottom value=0.1uF
C70 "GCM155R71E103KA37D" 0402 1673.3,779.65 r270 top value=0.01uF
C71 "GRM155R71E104KE14D" 0402 1764.9,1345.15 r90 top value=0.1uF
C72 "GRM155R71E104KE14D" 0402 1788.14,858.41 r0 top value=0.1uF
C73 "GRM188R61C106MAALD" 0603 1785.43,1768.4 r270 top value=10uF
C74 "GRM21BR61E226ME44L" 0805_HV 1675.75,1703.67 r0 top value=22uF
C75 "GRM155R61A475MEAAD" 0402 437.28,1087.67 r270 top value=4.7uF
C76 "GRM033Z71C104KE14D" 0201 713.06,2365.44 r90 bottom value=0.1uF
C77 "GRM155R71E104KE14D" 0402 1850.39,2248.61 r180 top value=0.1uF
C78 "GRM033Z71C104KE14D" 0201 675.4,2365.44 r90 bottom value=0.1uF
C79 "GRM155C81E105KE11D" FP-GRM155C81E105KE11D_0402-MFG 2311.17,270.65 r90 top value=1µF
C80 "GRM155R71E104KE14D" 0402 2448.59,281.51 r90 top value=0.1uF
C81 "GRM155R61E225KE11D" "FP-GRM155R61E225KE11D_0402 (1005 metric)-MFG" 1987.21,1229.68 r270 bottom value=2.2µF
C82 "GRM155R61A475MEAAD" 0402 1883.16,1254.92 r0 bottom value=4.7uF
C83 "GRM1555C1H102JA01D" 0402 2445.22,161.4 r0 top value=1000pF
C84 "GRM31CR61E476ME44K" FP-GRM31CR61E476ME44K_1206-MFG 2722.76,208.83 r0 top value=47µF
C85 "GRM31CR61E476ME44K" FP-GRM31CR61E476ME44K_1206-MFG 2722.33,121.28 r0 top value=47µF
C86 "GRM1555C1H102JA01D" 0402 1942.33,1376.14 r0 top value=1000pF
C87 "GRM21BR61E226ME44L" 0805_HV 1927.49,1444.43 r180 top value=22uF
C88 "GRM21BR61E226ME44L" 0805_HV 1970.98,1482.8 r180 bottom value=22uF
C89 "GRM21BR61E226ME44L" 0805_HV 1927.45,1532.65 r180 top value=22uF
C90 "GRM21BR61E226ME44L" 0805_HV 1971.46,1572.06 r180 bottom value=22uF
C91 "GRM155R71E104KE14D" 0402 1963.59,1367.88 r0 bottom value=0.1uF
C92 "GRM155R71E104KE14D" 0402 2607.99,438.59 r180 top value=0.1uF
C93 "GRM155R71E104KE14D" 0402 1963.59,1415.34 r0 bottom value=0.1uF
C94 "GRM31CR61E476ME44K" FP-GRM31CR61E476ME44K_1206-MFG 1959.35,658.09 r270 bottom value=47µF
C95 "GRM155R71E104KE14D" 0402 2066.95,1374.47 r0 top value=0.1uF
C96 "GRM155R61A106ME18D" FP-GRM155R61A106ME18D_0402-MFG 2864.74,429.38 r180 top value=10µF
C97 "GRM21BR61H106KE43L" FP-GRM21BR61H106KE43L_0805-MFG 2076.72,819.06 r0 top value=10µF
C98 "GRM155R71E104KE14D" 0402 2063.21,873.55 r0 top value=0.1uF
C99 "GRM155R71E104KE14D" 0402 2087.28,986.01 r90 bottom value=0.1uF
C100 "GRM21BR61E226ME44L" 0805_HV 2736.77,574.77 r180 top value=22uF
C101 "GRM21BR61H106KE43L" FP-GRM21BR61H106KE43L_0805-MFG 2143.85,970.91 r90 bottom value=10µF
C102 "GJM1555C1H470JB01D" FP-GJM1555C1H470JB01D_0402-MFG 2841.66,575.23 r270 top value=47pF
C103 "GRM1555C1H102JA01D" 0402 2912.53,569.48 r180 top value=1000pF
C104 "GRM21BR61H106KE43L" FP-GRM21BR61H106KE43L_0805-MFG 2066.55,1431.78 r0 top value=10µF
C105 "GRM155R71H104KE14D" FP-GRM155R71H104KE14D_0402-MFG 1526.37,2372.94 r180 bottom value=100nF
C107 "GRM21BR61H106KE43L" FP-GRM21BR61H106KE43L_0805-MFG 2114.47,1274.79 r180 bottom value=10µF
C109 "GRM21BR61H106KE43L" FP-GRM21BR61H106KE43L_0805-MFG 2269.71,815.79 r0 top value=10µF
C111 "GRM21BR61H106KE43L" FP-GRM21BR61H106KE43L_0805-MFG 2242.77,1308.26 r270 bottom value=10µF
C112 "GRM155R71E104KE14D" 0402 2197.22,1377.5 r0 top value=0.1uF
C113 "GRM155R71E104KE14D" 0402 2256.06,874.92 r0 top value=0.1uF
C114 "GRM155R71E104KE14D" 0402 2235.75,1413.17 r90 bottom value=0.1uF
C115 "GRM155R71E104KE14D" 0402 127.8,477.35 r270 top value=0.1uF
C116 "GRM155C81E105KE11D" FP-GRM155C81E105KE11D_0402-MFG 82.8,485.22 r270 top value=1µF
C117 "GRM155R71H104KE14D" FP-GRM155R71H104KE14D_0402-MFG 891.14,2125.81 r90 top value=100nF
C118 "GRM155R71H104KE14D" FP-GRM155R71H104KE14D_0402-MFG 172.58,2214.77 r180 top value=100nF
C119 "GRM155R71H104KE14D" FP-GRM155R71H104KE14D_0402-MFG 3003.75,2232.13 r180 top value=100nF
C120 "GRM155R71H104KE14D" FP-GRM155R71H104KE14D_0402-MFG 124.44,2058 r90 bottom value=100nF
C121 "GRM155R71H104KE14D" FP-GRM155R71H104KE14D_0402-MFG 2960.04,2176.53 r0 bottom value=100nF
C122 "GRM155R71E104KE14D" 0402 1434.54,674.05 r270 top value=0.1uF
C123 "GRM155R61A475MEAAD" 0402 1190.62,889.41 r180 bottom value=4.7uF
C124 "GRM033Z71C104KE14D" 0201 1139.23,978.34 r180 bottom value=0.1uF
C125 "GRM033Z71C104KE14D" 0201 1139.23,942.32 r180 bottom value=0.1uF
C126 "GRM033Z71C104KE14D" 0201 1153.6,910.2 r0 top value=0.1uF
C127 "GRM033Z71C104KE14D" 0201 1066.4,962.24 r90 top value=0.1uF
C128 "GRM155R61A475MEAAD" 0402 1152.81,965.15 r0 top value=4.7uF
C129 "GRM188R61C106MAALD" 0603 225.69,584.5 r0 top value=10uF
C130 "GCM155R71E103KA37D" 0402 562.32,618.15 r0 top value=0.01uF
C131 "GRM033Z71C104KE14D" 0201 677.11,1845.49 r0 top value=0.1uF
C132 "GRM155R71H682KA88D" 0402 1659.81,1919.18 r90 top value=6800pF
C137 "GRM155R71H104KE14D" FP-GRM155R71H104KE14D_0402-MFG 149.02,1120.78 r180 top value=100nF
C138 "GRM155R71H104KE14D" FP-GRM155R71H104KE14D_0402-MFG 397.38,1061.46 r90 top value=100nF
C139 "GRM155R71H104KE14D" FP-GRM155R71H104KE14D_0402-MFG 245.95,809.24 r180 top value=100nF
C140 "GRM155R71H104KE14D" FP-GRM155R71H104KE14D_0402-MFG 149.02,1085.78 r180 top value=100nF
C141 "GRM033Z71C104KE14D" 0201 335.2,1318.84 r270 top value=0.1uF
C152 "GRM155R71H104KE14D" FP-GRM155R71H104KE14D_0402-MFG 649.1,645.23 r180 top value=100nF
C153 "GRM155R61A475MEAAD" 0402 866.92,956.98 r0 bottom value=4.7uF
C154 "GRM033Z71C104KE14D" 0201 1188.84,991.41 r90 bottom value=0.1uF
C155 "GRM155R71H104KE14D" FP-GRM155R71H104KE14D_0402-MFG 1002.73,1994.51 r270 top value=100nF
C156 "GRM155R71H104KE14D" FP-GRM155R71H104KE14D_0402-MFG 2887.95,840.27 r0 bottom value=100nF
C157 "GRM155R71H104KE14D" FP-GRM155R71H104KE14D_0402-MFG 3021.31,906.96 r0 bottom value=100nF
C158 "GRM155R71H104KE14D" FP-GRM155R71H104KE14D_0402-MFG 1284.9,1989.51 r270 top value=100nF
C159 "GRM155R71H104KE14D" FP-GRM155R71H104KE14D_0402-MFG 1842.64,2378.25 r0 top value=100nF
C160 "GRM155R71H104KE14D" FP-GRM155R71H104KE14D_0402-MFG 1831.14,2002.06 r180 top value=100nF
C161 "GRM155R71H104KE14D" FP-GRM155R71H104KE14D_0402-MFG 1309.22,2084.47 r270 bottom value=100nF
C167 "GRM31CR61E476ME44K" FP-GRM31CR61E476ME44K_1206-MFG 1871.03,658.09 r270 bottom value=47µF
C168 "GRM31CR61E476ME44K" FP-GRM31CR61E476ME44K_1206-MFG 1959.35,658.09 r270 top value=47µF
C169 "GRM31CR61E476ME44K" FP-GRM31CR61E476ME44K_1206-MFG 1928.84,1617.81 r0 top value=47µF
C174 "GRM155R71H104KE14D" FP-GRM155R71H104KE14D_0402-MFG 3050.22,1082.55 r270 bottom value=100nF
D2 "150060VS75000" WL-SMCW_GREEN 1525.61,838.39 r90 top value=Green
D3 "150060VS75000" WL-SMCW_GREEN 1388.78,838.39 r90 top value=Green
D4 "150060VS75000" WL-SMCW_GREEN 2727.29,2214.42 r180 top value=Green
D5 "150060VS75000" WL-SMCW_GREEN 2611.62,759.91 r180 top value=Green
D6 "150060VS75000" WL-SMCW_GREEN 2859.8,2098.66 r90 top value=Green
D7 "150060VS75000" WL-SMCW_GREEN 2486.37,2258.07 r0 top value=Green
D8 "150060VS75000" WL-SMCW_GREEN 2611.1,871.87 r180 top value=Green
D9 "150040RS73220" FP-150040RS73220_0402-MFG 2910.91,1033.04 r180 top
D10 "150040RS73220" FP-150040RS73220_0402-MFG 2938.58,1674.75 r180 top
Designator7 "Comment" BRAKE_WAY_HOLES1X3 602.96,-39.37 r0 top
Designator7_1 "Comment" BRAKE_WAY_HOLES1X3 602.96,2539.37 r0 bottom
Designator8 "Comment" BRAKE_WAY_HOLES1X3 1554.97,-39.37 r0 top
Designator8_1 "Comment" BRAKE_WAY_HOLES1X3 1554.97,2539.37 r0 bottom
Designator9 "Comment" BRAKE_WAY_HOLES1X3 2507.27,-39.37 r180 bottom
Designator9_1 "Comment" BRAKE_WAY_HOLES1X3 2507.27,2539.37 r180 top
FB1 "BLM18EG121SN1D" FP-BLM18EG121SN1D_0603-MFG 1046.27,943.89 r0 bottom
FB2 "BLM18EG121SN1D" FP-BLM18EG121SN1D_0603-MFG 685.56,1091.97 r0 bottom
FB3 "BLM18EG101TN1D" FP-BLM18EG101TN1D_0603-MFG 82.8,563.11 r270 top
FID1 "Fiducial" FIDUCIAL10-20 104,63.04 r90 top
FID2 "Fiducial" FIDUCIAL10-20 104,63.04 r90 bottom
FID3 "Fiducial" Fiducial10-20 104,2436.97 r90 top
FID4 "Fiducial" FIDUCIAL10-20 104,2436.97 r90 bottom
FID5 "Fiducial" FIDUCIAL10-20 2396.89,63.04 r90 top
FID6 "Fiducial" FIDUCIAL10-20 2396.89,63.04 r90 bottom
FID7 "Fiducial" FIDUCIAL10-20 350,-204.34 r90 bottom (schematic designator FID2)
FID8 "Fiducial" FIDUCIAL10-20 2760.24,-204.34 r270 bottom (schematic designator FID2)
FID9 "Fiducial" FIDUCIAL10-20 2760.24,2704.34 r270 bottom (schematic designator FID2)
FID10 "Fiducial" FIDUCIAL10-20 350,2704.34 r90 bottom (schematic designator FID2)
FID12 "Fiducial" FIDUCIAL10-20 350,2704.34 r90 top (schematic designator FID2)
FID13 "Fiducial" FIDUCIAL10-20 2760.24,2704.34 r90 top (schematic designator FID2)
FID14 "Fiducial" FIDUCIAL10-20 350,-204.34 r90 top (schematic designator FID2)
FID15 "Fiducial" FIDUCIAL10-20 2760.24,-204.34 r90 top (schematic designator FID2)
J1 "QSH-060-01-L-D-A" CONN_QSH-060-01-L-D-A 1395,295 r180 bottom locked
J2 "QSH-060-01-L-D-A" CONN_QSH-060-01-L-D-A 310,1110 r270 bottom locked
J3 "QSH-060-01-L-D-A" CONN_QSH-060-01-L-D-A 2475,1110 r90 bottom locked
J5 "QSH-030-01-L-D-A" FP-QSH-030-01-L-D-A_CONN_60-MFG 2475.38,1503.72 r270 top locked
J7 "TSM-108-01-L-DV-008-P-TR" FP-TSM-108-01-L-DV-008-P-TR_HDR15-MFG 1716.47,233.62 r180 top locked
J8 "61300311121" WURTH_61300311121 2495.83,2364.93 r0 top
J9 "61300311121" WURTH_61300311121 2857.95,2362.59 r180 top
L1 "IHLP2020BZER2R2M01" IHLP-2020BZ 1668.25,1118.22 r90 top value=2.2uH
L2 "XGL4030-102MEC" FP-XGL4030-102MEC_SMD_IND_4MM0_4MM0-MFG 1510.45,1744.74 r270 top value=1uH
L3 "DFE252012P-1R5M=P2" DFE252012P 2711.55,299.46 r0 top value=1.5uH
Logo1 "CE Mark" CE_MARK_5MM 1124,693 r180 bottom
Logo2 "Texas Instruments" TI_STACKED_OVERLAY_SMALL 2979.09,1573.92 r90 bottom
Logo3 "FCC disclaimer" FCC_DISCLAIMER -2201.63,1197 r90 bottom
Logo4 "WEEE logo" WEEE_Minimum 637.46,2039.56 r180 bottom
MH1 "MTG_NoPads" MTG_159mil 410,155 r0 top locked
MH2 "MTG_NoPads" MTG_159mil 2170,590 r0 top locked
MH3 "MTG_NoPads" MTG_159mil 2380,2060 r0 top locked
MH4 "MTG_NoPads" MTG_159mil 410,2060 r0 top locked
Q2 "BSS123W-7-F" SOT-323 2777.11,2121.42 r90 top value=100V
Q3 "IRLML6401TRPBF" SOT-23 2803.98,1033.04 r0 top value=-12V
Q4 "IRLML6401TRPBF" SOT-23 2918.89,1569.35 r90 top value=-12V
R1 "CRCW04024K70JNED" 0402 1810.09,491.94 r0 top value=4.7k
R2 "RC0402JR-0710KL" FP-RC0402JR-0710KL_0402-MFG 1711.47,472.26 r90 top value=10k
R3 "ERJ-2GE0R00X" FP-ERJ-2GE0R00X_0402-MFG 319.67,390.39 r270 top value=0
R4 "ERJ-1GN0R00C" 0201 1380.15,1039.53 r0 bottom value=0
R5 "ERJ-2GE0R00X" FP-ERJ-2GE0R00X_0402-MFG 2758.72,1529.81 r0 bottom value=0
R6 "ERJ-1GN0R00C" 0201 1519.07,1439.81 r90 bottom value=0
R7 "ERJ-1GN0R00C" 0201 1567.51,1445.7 r90 bottom value=0
R8 "ERJ-2GE0R00X" FP-ERJ-2GE0R00X_0402-MFG 2674,1533 r0 bottom value=0
R9 "ERJ-2GE0R00X" FP-ERJ-2GE0R00X_0402-MFG 1057.21,1154.49 r270 bottom value=0
R10 "ERJ-2GE0R00X" FP-ERJ-2GE0R00X_0402-MFG 689.14,1162.37 r180 bottom value=0
R11 "ERJ-2GE0R00X" FP-ERJ-2GE0R00X_0402-MFG 1256.96,1308.66 r180 bottom value=0
R12 "AC0402FR-0710KL" 0402 611.15,873.83 r270 bottom value=10.0k
R13 "CRCW04022K67FKED" 0402 711.15,873.83 r90 bottom value=2.67k
R14 "ERJ-2GEJ102X" 0402 1673.3,896.89 r270 top value=1.0k
R15 "ERJ-2GE0R00X" FP-ERJ-2GE0R00X_0402-MFG 1719.52,878.58 r270 top value=0
R16 "AC0402FR-0710KL" 0402 1756.86,797.34 r0 bottom value=10.0k
R17 "CRCW04023K90JNED" 0402 1709.61,848.2 r0 bottom value=3.9k
R18 "ERJ-2GE0R00X" FP-ERJ-2GE0R00X_0402-MFG 1753.27,889.41 r180 bottom value=0
R19 "RC0402JR-0710KL" FP-RC0402JR-0710KL_0402-MFG 2107.45,1653.41 r270 top value=10k
R20 "RC0402JR-0710KL" FP-RC0402JR-0710KL_0402-MFG 2073.09,1374.47 r0 bottom value=10k
R21 "RC0402JR-0710KL" FP-RC0402JR-0710KL_0402-MFG 2049.53,1507.27 r0 top value=10k
R22 "RC0402JR-0710KL" FP-RC0402JR-0710KL_0402-MFG 2028.96,1563.99 r90 top value=10k
R23 "ERJ-2GE0R00X" FP-ERJ-2GE0R00X_0402-MFG 2185.94,843.13 r90 top value=0
R24 "RC0201FR-0722RL" 0201 2138.65,1495.75 r0 bottom value=22.0
R25 "ERJ-2GE0R00X" FP-ERJ-2GE0R00X_0402-MFG 2155.94,1413.47 r90 bottom value=0
R26 "ERJ-1GN0R00C" 0201 2754.95,1875.9 r180 top value=0
R27 "ERJ-2GE0R00X" FP-ERJ-2GE0R00X_0402-MFG 1689.83,1778.14 r90 bottom value=0
R28 "ERJ-2GE0R00X" FP-ERJ-2GE0R00X_0402-MFG 2024.45,986.01 r90 bottom value=0
R29 "AC0402FR-0710KL" 0402 1661.02,1635.21 r180 top value=10.0k
R30 "CRCW0402100KJNED" 0402 1559.58,1884.88 r180 top value=100k
R31 "ERJ-1GN0R00C" 0201 2656.82,1189.19 r90 top value=0
R32 "CRCW0402100KJNED" 0402 1559.58,1937.28 r0 top value=100k
R33 "AC0402FR-0710KL" 0402 1768.26,1635.21 r180 top value=10.0k
R34 "CRCW0402301KFKED" 0402 2806.82,380.42 r180 top value=301k
R35 "ERJ-2GE0R00X" FP-ERJ-2GE0R00X_0402-MFG 1702.27,1915.71 r270 top value=0
R36 "ERJ-2GE0R00X" FP-ERJ-2GE0R00X_0402-MFG 491.32,449.79 r180 top value=0
R37 "RC0402JR-0710KL" FP-RC0402JR-0710KL_0402-MFG 1557.36,1845.99 r180 top value=10k
R38 "ERJ-2GEJ330X" FP-ERJ-2GEJ330X_0402-MFG 1199.16,1697.03 r270 top value=33
R39 "ERJ-2GEJ330X" FP-ERJ-2GEJ330X_0402-MFG 1229.58,1697.54 r270 top value=33
R40 "CRCW04024K70JNED" 0402 2776.65,1635.38 r270 top value=4.7k
R41 "RC0402JR-0710KL" FP-RC0402JR-0710KL_0402-MFG 1383.53,2065.26 r90 bottom value=10k
R42 "RC0402JR-0710KL" FP-RC0402JR-0710KL_0402-MFG 2274.52,202.01 r0 top value=10k
R43 "FC4L16R010FER" FP-FC4L16R010FER_0306-MFG 1643.04,1584.58 r270 top value=10m
R44 "FC4L16R010FER" FP-FC4L16R010FER_0306-MFG 2062.8,1688.73 r180 bottom value=10m
R45 "ERJ-2GE0R00X" FP-ERJ-2GE0R00X_0402-MFG 2629.27,583.02 r270 top value=0
R46 "RC0402JR-0710KL" FP-RC0402JR-0710KL_0402-MFG 373.55,371.39 r0 top value=10k
R47 "CRCW04021K20JNED" 0402 1548.35,941.18 r270 bottom value=1.2k
R48 "CRCW04021K20JNED" 0402 1388.78,841.74 r270 bottom value=1.2k
R49 "CRCW04024K70JNED" 0402 1967.63,2348.61 r0 bottom value=4.7k
R50 "CRCW04024K70JNED" 0402 1967.63,2398.61 r0 bottom value=4.7k
R51 "RC0402JR-0710KL" FP-RC0402JR-0710KL_0402-MFG 372.81,404.71 r180 top value=10k
R52 "ERJ-2GE0R00X" FP-ERJ-2GE0R00X_0402-MFG 410,629.77 r0 top value=0
R53 "ERJ-2GE0R00X" FP-ERJ-2GE0R00X_0402-MFG 575.49,1024.24 r0 top value=0
R54 "RC0402JR-0710KL" FP-RC0402JR-0710KL_0402-MFG 769.1,1790.23 r180 top value=10k
R55 "RC0402JR-0710KL" FP-RC0402JR-0710KL_0402-MFG 741.14,2129.75 r270 top value=10k
R56 "ERJ-2GE0R00X" FP-ERJ-2GE0R00X_0402-MFG 815.81,2121.54 r180 top value=0
R57 "CRCW0402130RFKED" 0402 2695.79,2128.2 r90 top value=130
R58 "RC0201JR-7D300RL" 0201 2515.84,759.91 r0 top value=300
R59 "CRCW0402100RFKED" 0402 2267.07,1867.96 r90 top value=100
R60 "ERJ-2GEJ330X" FP-ERJ-2GEJ330X_0402-MFG 2698.36,1804.15 r180 top value=33
R61 "ERJ-2GEJ330X" FP-ERJ-2GEJ330X_0402-MFG 2677.37,1942.55 r180 bottom value=33
R62 "ERJ-2GEJ330X" FP-ERJ-2GEJ330X_0402-MFG 2859.8,1764.32 r180 top value=33
R63 "ERJ-2GEJ330X" FP-ERJ-2GEJ330X_0402-MFG 2702.48,1887.37 r180 bottom value=33
R64 "ERJ-1GN0R00C" 0201 2691.17,1712.47 r180 top value=0
R65 "RC0201FR-0722RL" 0201 2673.83,1923.29 r0 top value=22.0
R66 "RC0402FR-0710RL" FP-RC0402FR-0710RL_0402-MFG 177.67,2039.56 r180 bottom value=10
R67 "RC0402FR-0710RL" FP-RC0402FR-0710RL_0402-MFG 2938.78,2115.98 r90 bottom value=10
R68 "CRCW0402130RFKED" 0402 2859.8,2212.56 r270 top value=130
R69 "ERJ-2GE0R00X" FP-ERJ-2GE0R00X_0402-MFG 1964.19,2298.61 r0 bottom value=0
R70 "RC0402FR-0710RL" FP-RC0402FR-0710RL_0402-MFG 177.67,2081.01 r180 bottom value=10
R71 "RC0402FR-0710RL" FP-RC0402FR-0710RL_0402-MFG 2980.39,2115.98 r90 bottom value=10
R72 "CRCW0402130RFKED" 0402 2596.3,2258.53 r180 top value=130
R73 "ERJ-2GE0R00X" FP-ERJ-2GE0R00X_0402-MFG 999.35,1043.74 r0 bottom value=0
R74 "ERJ-2GE0R00X" FP-ERJ-2GE0R00X_0402-MFG 1741.47,471.77 r90 top value=0
R75 "ERJ-2GE0R00X" FP-ERJ-2GE0R00X_0402-MFG 1031.59,867.87 r270 top value=0
R76 "ERJ-2GE0R00X" FP-ERJ-2GE0R00X_0402-MFG 1191.71,1570.78 r0 bottom value=0
R77 "ERJ-2GE0R00X" FP-ERJ-2GE0R00X_0402-MFG 1240.7,1038.54 r270 bottom value=0
R78 "ERJ-2GE0R00X" FP-ERJ-2GE0R00X_0402-MFG 1243.71,954.46 r270 bottom value=0
R79 "ERJ-1GN0R00C" 0201 1281.43,876.51 r0 bottom value=0
R80 "RC0402JR-0710KL" FP-RC0402JR-0710KL_0402-MFG 599.18,1754.31 r0 top value=10k
R81 "RC0402JR-0710KL" FP-RC0402JR-0710KL_0402-MFG 668.63,1895.71 r270 top value=10k
R82 "RC0402JR-0710KL" FP-RC0402JR-0710KL_0402-MFG 2313.89,169.51 r0 top value=10k
R83 "ERJ-1GN0R00C" 0201 1283.41,1625.99 r180 top value=0
R84 "ERJ-1GN0R00C" 0201 417.42,1258.48 r90 top value=0
R85 "ERJ-1GN0R00C" 0201 1276.95,1685.63 r180 top value=0
R86 "RCC040210R0FKED" FP-RCC040210R0FKED_0402-MFG 2019.96,1851.9 r180 top value=10
R87 "RCC040210R0FKED" FP-RCC040210R0FKED_0402-MFG 2100.25,1847.43 r180 top value=10
R88 "RCC040210R0FKED" FP-RCC040210R0FKED_0402-MFG 2768.17,1434.06 r180 bottom value=10
R89 "RCC040210R0FKED" FP-RCC040210R0FKED_0402-MFG 2100.25,1787.43 r180 top value=10
R90 "RCC040210R0FKED" FP-RCC040210R0FKED_0402-MFG 2159.79,1713.93 r180 top value=10
R91 "RCC040210R0FKED" FP-RCC040210R0FKED_0402-MFG 2134.23,2106.51 r270 bottom value=10
R92 "RCC040210R0FKED" FP-RCC040210R0FKED_0402-MFG 2159.79,1648.62 r180 top value=10
R93 "RCC040210R0FKED" FP-RCC040210R0FKED_0402-MFG 2038.44,1945.34 r0 top value=10
R94 "RCC040210R0FKED" FP-RCC040210R0FKED_0402-MFG 2159.79,1588.62 r180 top value=10
R95 "RCC040210R0FKED" FP-RCC040210R0FKED_0402-MFG 2795.77,1305.1 r270 bottom value=10
R96 "ERJ-2GE0R00X" FP-ERJ-2GE0R00X_0402-MFG 2702.18,1304.05 r90 bottom value=0
R97 "RCC040210R0FKED" FP-RCC040210R0FKED_0402-MFG 2159.79,1528.62 r180 top value=10
R98 "RCC040210R0FKED" FP-RCC040210R0FKED_0402-MFG 2198.4,2126.9 r90 top value=10
R99 "RCC040210R0FKED" FP-RCC040210R0FKED_0402-MFG 1922,2010 r90 bottom value=10
R100 "RCC040210R0FKED" FP-RCC040210R0FKED_0402-MFG 2065.1,1900.02 r270 bottom value=10
R101 "RCC040210R0FKED" FP-RCC040210R0FKED_0402-MFG 2099.5,2028.45 r90 bottom value=10
R102 "RCC040210R0FKED" FP-RCC040210R0FKED_0402-MFG 2009.4,1909.03 r0 top value=10
R103 "RCC040210R0FKED" FP-RCC040210R0FKED_0402-MFG 2166.21,2127.06 r90 top value=10
R104 "ERJ-2GEJ152X" FP-ERJ-2GEJ152X_0402-MFG 1522.99,1215.29 r0 top value=1.5k
R105 "ERJ-2GEJ152X" FP-ERJ-2GEJ152X_0402-MFG 1521.63,1246.63 r0 top value=1.5k
R106 "RC0201FR-0722RL" 0201 590.65,1647.18 r0 top value=22.0
R107 "RC0201FR-0722RL" 0201 559.51,1609.96 r0 top value=22.0
R108 "ERJ-1GN0R00C" 0201 1439.18,1255.96 r180 top value=0
R109 "RC0201FR-0722RL" 0201 633.53,1489.43 r0 bottom value=22.0
R110 "ERJ-1GN0R00C" 0201 1439.18,1219.84 r180 top value=0
R111 "RC0201FR-0722RL" 0201 590.65,1498.29 r0 top value=22.0
R112 "RC0201FR-0722RL" 0201 590.65,1572.73 r0 top value=22.0
R113 "RC0201FR-0722RL" 0201 559.51,1535.51 r0 top value=22.0
R114 "RC0201FR-0722RL" 0201 590.65,1423.85 r0 top value=22.0
R115 "RC0201FR-0722RL" 0201 632.59,1440.58 r0 bottom value=22.0
R116 "RC0201FR-0722RL" 0201 559.51,1461.07 r0 top value=22.0
R117 "RC0201FR-0722RL" 0201 569.56,1467.83 r0 bottom value=22.0
R118 "RC0201FR-0722RL" 0201 590.65,1349.4 r0 top value=22.0
R119 "ERJ-1GN0R00C" 0201 1320.67,1202.2 r180 bottom value=0
R120 "RC0201FR-0722RL" 0201 590.65,1274.96 r0 top value=22.0
R121 "ERJ-1GN0R00C" 0201 1323.8,1238.42 r180 bottom value=0
R122 "ERJ-1GN0R00C" 0201 1503.86,1400.85 r180 top value=0
R123 "RC0201FR-0722RL" 0201 559.51,1386.62 r0 top value=22.0
R124 "ERJ-1GN0R00C" 0201 1508.32,1300.11 r270 bottom value=0
R125 "RC0201FR-0722RL" 0201 632.28,1390.16 r0 bottom value=22.0
R126 "ERJ-1GN0R00C" 0201 1383.54,1334.2 r270 top value=0
R127 "RC0201FR-0722RL" 0201 568.8,1417.55 r0 bottom value=22.0
R128 "RC0201FR-0722RL" 0201 559.51,1312.18 r0 top value=22.0
R129 "ERJ-2GE0R00X" FP-ERJ-2GE0R00X_0402-MFG 851.09,1681.87 r270 top value=0
R130 "RC0201FR-0722RL" 0201 569.18,1365.25 r0 bottom value=22.0
R131 "RC0201FR-0722RL" 0201 590.65,1200.51 r0 top value=22.0
R132 "ERJ-2GE0R00X" FP-ERJ-2GE0R00X_0402-MFG 815.09,1681.87 r270 top value=0
R133 "RC0201FR-0722RL" 0201 559.51,1237.73 r0 top value=22.0
R134 "RC0201FR-0722RL" 0201 559.51,1163.29 r0 top value=22.0
R135 "RC0201FR-0722RL" 0201 632.57,1342.48 r0 bottom value=22.0
R136 "RC0201FR-0722RL" 0201 590.65,1126.07 r0 top value=22.0
R137 "ERJ-1GN0R00C" 0201 1399.86,1533.91 r180 top value=0
R138 "ERJ-1GN0R00C" 0201 457.42,1258.48 r90 top value=0
R139 "ERJ-1GN0R00C" 0201 1391.57,1570.23 r180 top value=0
R140 "ERJ-2GE0R00X" FP-ERJ-2GE0R00X_0402-MFG 787.59,950.62 r90 bottom value=0
R141 "ERJ-1GN0R00C" 0201 1370.22,1516.39 r180 bottom value=0
R142 "ERJ-1GN0R00C" 0201 1399.86,1498.91 r180 top value=0
R143 "RC0201FR-0722RL" 0201 559.51,1088.84 r0 top value=22.0
R144 "RC0201FR-0722RL" 0201 568.8,1319.64 r0 bottom value=22.0
R145 "ERJ-1GN0R00C" 0201 1370.22,1548.7 r180 bottom value=0
R146 "RC0201FR-0722RL" 0201 568.8,1270.64 r0 bottom value=22.0
R147 "RC0201FR-0722RL" 0201 632.28,1296.22 r0 bottom value=22.0
R148 "ERJ-1GN0R00C" 0201 864.06,1030.78 r270 bottom value=0
R149 "ERJ-2GE0R00X" FP-ERJ-2GE0R00X_0402-MFG 2009.4,1794.21 r180 bottom value=0
R150 "ERJ-2GE0R00X" FP-ERJ-2GE0R00X_0402-MFG 2100.25,1847.43 r180 bottom value=0
R151 "ERJ-2GE0R00X" FP-ERJ-2GE0R00X_0402-MFG 2769.4,1443.2 r90 top value=0
R152 "ERJ-2GE0R00X" FP-ERJ-2GE0R00X_0402-MFG 2097.38,1770.34 r180 bottom value=0
R153 "ERJ-2GE0R00X" FP-ERJ-2GE0R00X_0402-MFG 2169.4,2124.45 r270 bottom value=0
R154 "ERJ-2GE0R00X" FP-ERJ-2GE0R00X_0402-MFG 2207.4,2030.73 r90 bottom value=0
R155 "ERJ-2GE0R00X" FP-ERJ-2GE0R00X_0402-MFG 2009.11,1855.57 r180 bottom value=0
R156 "ERJ-2GE0R00X" FP-ERJ-2GE0R00X_0402-MFG 2138.04,1962.95 r180 bottom value=0
R157 "CRCW04024K70JNED" 0402 893.54,1699.9 r90 top value=4.7k
R158 "CRCW04024K70JNED" 0402 707.35,1641.8 r180 bottom value=4.7k
R159 "ERJ-2GE0R00X" FP-ERJ-2GE0R00X_0402-MFG 1897.01,1937.87 r90 bottom value=0
R160 "RC0201JR-7D300RL" 0201 2521.67,871.87 r0 top value=300
R161 "ERJ-2GE0R00X" FP-ERJ-2GE0R00X_0402-MFG 2136.12,1884.68 r180 bottom value=0
R162 "ERJ-2GE0R00X" FP-ERJ-2GE0R00X_0402-MFG 867.9,1614.18 r270 bottom value=0
R163 "ERJ-2GE0R00X" FP-ERJ-2GE0R00X_0402-MFG 2159.79,1648.62 r180 bottom value=0
R164 "ERJ-2GE0R00X" FP-ERJ-2GE0R00X_0402-MFG 2159.79,1588.62 r180 bottom value=0
R165 "ERJ-2GE0R00X" FP-ERJ-2GE0R00X_0402-MFG 720.37,877.74 r90 top value=0
R166 "ERJ-2GE0R00X" FP-ERJ-2GE0R00X_0402-MFG 725.2,1004.78 r180 top value=0
R167 "ERJ-2GE0R00X" FP-ERJ-2GE0R00X_0402-MFG 2754.95,1305.1 r270 bottom value=0
R168 "ERJ-2GE0R00X" FP-ERJ-2GE0R00X_0402-MFG 689.31,877.74 r90 top value=0
R169 "ERJ-2GE0R00X" FP-ERJ-2GE0R00X_0402-MFG 2175.24,1528.68 r180 bottom value=0
R170 "ERJ-2GE0R00X" FP-ERJ-2GE0R00X_0402-MFG 2134.23,2030.52 r90 bottom value=0
R171 "ERJ-2GE0R00X" FP-ERJ-2GE0R00X_0402-MFG 2159.79,1713.93 r180 bottom value=0
R172 "ERJ-2GE0R00X" FP-ERJ-2GE0R00X_0402-MFG 2682,1258.87 r0 bottom value=0
R173 "ERJ-2GE0R00X" FP-ERJ-2GE0R00X_0402-MFG 1978.68,2003.02 r270 bottom value=0
R174 "ERJ-2GE0R00X" FP-ERJ-2GE0R00X_0402-MFG 599.82,1053.86 r0 top value=0
R175 "RC0201FR-0749K9L" 0201 500.38,848.86 r0 top value=49.9k
R176 "RC0201FR-0749K9L" 0201 501.55,960.62 r0 top value=49.9k
R177 "RC0201FR-0749K9L" 0201 501.02,1013.96 r0 top value=49.9k
R178 "RC0201FR-0749K9L" 0201 308.96,1185.97 r90 top value=49.9k
R179 "RC0201FR-0749K9L" 0201 246.98,1185.97 r90 top value=49.9k
R180 "CRCW04024K70JNED" 0402 199,1205.66 r90 top value=4.7k
R181 "RC0201FR-0749K9L" 0201 500.78,893.76 r0 top value=49.9k
R182 "RC0201FR-0749K9L" 0201 363.94,1164.69 r0 top value=49.9k
R183 "RC0402JR-0710KL" FP-RC0402JR-0710KL_0402-MFG 118.81,1220.75 r0 top value=10k
R184 "RC0402JR-0710KL" FP-RC0402JR-0710KL_0402-MFG 537.17,999.58 r270 bottom value=10k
